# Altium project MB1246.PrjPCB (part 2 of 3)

## Sheet ST_LINK_V2-1.SCHDOC: ST-LINK/V2-1
size A4; DocumentNumber: MB1246; Revision: B.2; SheetNumber: 15; SheetTotal: 17; Project: STM32H7x3I-EVAL
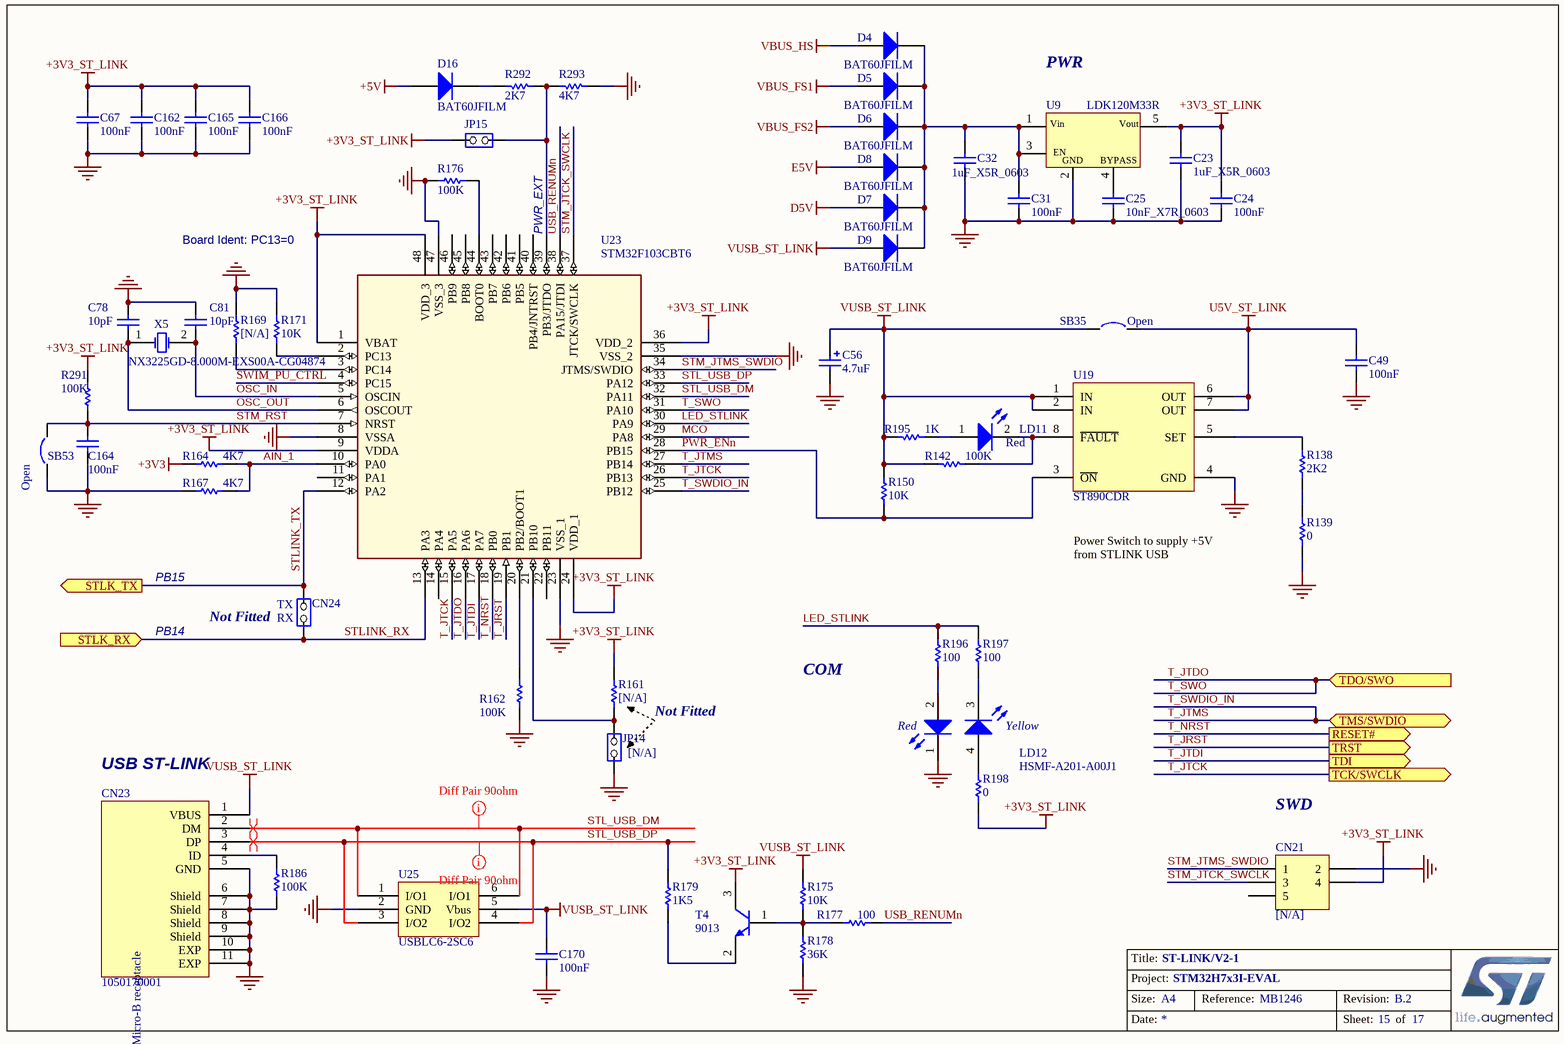
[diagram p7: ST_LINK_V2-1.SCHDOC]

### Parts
C23  1uF_X5R_0603  [0603C]
C24  100nF  [0603C]
C25  10nF_X7R_0603  [0603C]
C31  100nF  [0603C]
C32  1uF_X5R_0603  [0603C]
C49  100nF  [0603C]
C56  4.7uF  [TAN-A]
C67  100nF  [0603C]
C78  10pF  [0603C]
C81  10pF  [0603C]
C162  100nF  [0603C]
C164  100nF  [0603C]
C165  100nF  [0603C]
C166  100nF  [0603C]
C170  100nF  [0603C]
CN21  [N/A]  [HDR_2X3-1_2R54-6]
CN23  1050170001  [MICRO_USB_B_105017]
CN24  (no value)  [SIP2]
D4  BAT60JFILM  [SOD-323]
D5  BAT60JFILM  [SOD-323]
D6  BAT60JFILM  [SOD-323]
D7  BAT60JFILM  [SOD-323]
D8  BAT60JFILM  [SOD-323]
D9  BAT60JFILM  [SOD-323]
D16  BAT60JFILM  [SOD-323]
JP14  [N/A]  [SIP2]
JP15  (no value)  [SIP2]
LD11  Red  [0603D]
LD12  HSMF-A201-A00J1  [LED2_3528]
R138  2K2  [0402R]
R139  0  [0603R]
R142  100K  [0603R]
R150  10K  [0402R]
R161  [N/A]  [0603R]
R162  100K  [0603R]
R164  4K7  [0603R]
R167  4K7  [0603R]
R169  [N/A]  [0603R]
R171  10K  [0603R]
R175  10K  [0603R]
R176  100K  [0603R]
R177  100  [0603R]
R178  36K  [0603R]
R179  1K5  [0603R]
R186  100K  [0603R]
R195  1K  [0603R]
R196  100  [0603R]
R197  100  [0603R]
R198  0  [0603R]
R291  100K  [0603R]
R292  2K7  [0603R]
R293  4K7  [0603R]
SB35  Open  [SB_0603]
SB53  Open  [SB_0603]
T4  9013  [SOT-23]
U9  LDK120M33R  [SOT23-5]
U19  ST890CDR  [SOIC8_1R27_4R9X6]
U23  STM32F103CBT6  [LQFP48_0R5_9X9]
U25  USBLC6-2SC6  [SOT23-6L]
X5  NX3225GD-8.000M-EXS00A-CG04874  [XTAL_2SM_3R2X2R5_H1]

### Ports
RESET# (out), STLK_RX (in), STLK_TX (out), TCK/SWCLK (out), TDI (out), TDO/SWO (in), TMS/SWDIO (bidir), TRST (out)

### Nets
+3V3: R164.1
+3V3_ST_LINK: C23.1 C24.2 C67.2 C162.2 C165.2 C166.2 CN21.4 JP15.1(COMMON) R161.1 R198.2 R291.2 T4.3(C) U9.5(Vout) U23.1(VBAT) U23.9(VDDA) U23.24(VDD_1) U23.36(VDD_2) U23.48(VDD_3)
+5V: D16.1(A)
D5V: D7.1(A)
E5V: D8.1(A)
GND: C23.2 C24.1 C25.1 C31.1 C32.1 C49.1 C56.2 C67.1 C78.2 C81.2 C162.1 C164.1 C165.1 C166.1 C170.1 CN21.2 CN23.5(GND) CN23.6(Shield) CN23.7(Shield) CN23.8(Shield) CN23.9(Shield) CN23.10(EXP) CN23.11(EXP) JP14.1(COMMON) LD12.1(RED_cathode) R139.1 R162.1 R167.1 R169.1 R171.1 R176.1 R178.1 R186.2 R293.2 SB53.1 U9.2(GND) U19.4(GND) U23.8(VSSA) U23.23(VSS_1) U23.35(VSS_2) U23.47(VSS_3) U25.2(GND)
U5V_ST_LINK: C49.2 SB35.2 U19.6(OUT) U19.7(OUT)
VBUS_FS1: D5.1(A)
VBUS_FS2: D6.1(A)
VBUS_HS: D4.1(A)
VUSB_ST_LINK: C56.1 C170.2 CN23.1(VBUS) D9.1(A) R142.1 R150.1 R175.2 R195.1 SB35.1 U19.1(IN) U19.2(IN) U25.5(Vbus)
AIN_1: R164.2 R167.2 U23.10(PA0)
LED_STLINK: R196.1 R197.1 U23.30(PA9)
MCO: U23.29(PA8)
OSC_IN: C81.1 U23.5(OSCIN) X5.2(OSC2)
OSC_OUT: C78.1 U23.6(OSCOUT) X5.1(OSC1)
PWR_ENn: R150.2 U19.3(~{ON}) U23.28(PB15)
STL_USB_DM: CN23.2(DM) U23.32(PA11) U25.1(I/O1) U25.6(I/O1)
STL_USB_DP: CN23.3(DP) R179.1 U23.33(PA12) U25.3(I/O2) U25.4(I/O2)
STLINK_RX: CN24.1(COMMON) U23.13(PA3) ; port STLK_RX
STLINK_TX: CN24.2(NO) U23.12(PA2) ; port STLK_TX
STM_JTCK_SWCLK: CN21.3 U23.37(JTCK/SWCLK)
STM_JTMS_SWDIO: CN21.1 U23.34(JTMS/SWDIO)
STM_RST: C164.2 R291.1 SB53.2 U23.7(NRST)
SWIM_PU_CTRL: U23.4(PC15)
T_JRST: U23.19(PB1) ; port TRST  [project net PB4]
T_JTCK: U23.15(PA5) U23.26(PB13) ; port TCK/SWCLK  [project net PA14]
T_JTDI: U23.17(PA7) ; port TDI  [project net PA15]
T_JTDO: U23.16(PA6) U23.31(PA10) ; port TDO/SWO  [also labelled T_SWO]  [project net PB3]
T_JTMS: U23.25(PB12) U23.27(PB14) ; port TMS/SWDIO  [also labelled T_SWDIO_IN]  [project net PA13]
T_NRST: U23.18(PB0) ; port RESET#  [project net RESET#]
USB_RENUMn: R177.2 U23.38(PA15/JTDI)
NetC25_2: C25.2 U9.4(BYPASS)
NetC31_2: C31.2 C32.2 D4.2(K) D5.2(K) D6.2(K) D7.2(K) D8.2(K) D9.2(K) U9.1(Vin) U9.3(CE)
NetCN23_4: CN23.4(ID) R186.1
NetD16_2: D16.2(K) R292.1
NetJP14_2: JP14.2(NO) R161.2 U23.21(PB10)
NetJP15_2: JP15.2(NO) R292.2 R293.1 U23.39(PB3/JTDO)
NetLD11_1: LD11.1(A) R195.2
NetLD11_2: LD11.2(K) R142.2 U19.8(~{FAULT})
NetLD12_2: LD12.2(Red_anode) R196.2
NetLD12_3: LD12.3(YellowGreen_cathode) R197.2
NetLD12_4: LD12.4(YellowGreen_anode) R198.1
NetR138_1: R138.1 R139.2
NetR138_2: R138.2 U19.5(SET)
NetR162_2: R162.2 U23.20(PB2/BOOT1)
NetR169_2: R169.2 U23.3(PC14)
NetR171_2: R171.2 U23.2(PC13)
NetR175_1: R175.1 R177.1 R178.2 T4.1(B)
NetR176_2: R176.2 U23.44(BOOT0)
NetR179_2: R179.2 T4.2(E)

Not connected (* = marked no-connect by the designer): CN21 5; U23 11(PA1) 14(PA4) 22(PB11) 40(PB4/JNTRST) 41(PB5) 42(PB6) 43(PB7) 45(PB8) 46(PB9)

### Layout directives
differential pair: (no net found under the mark)
mark named Diff Pair 90ohm: STL_USB_DM, STL_USB_DP

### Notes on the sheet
- PWR
- Board Ident: PC13=0
- (near U23) PWR_EXT
- PB15
- Power Switch to supply +5V from STLINK USB
- PB14
- (near CN24) Not Fitted
- (near CN24) TX
- (near CN24) RX
- Not Fitted
- COM
- (near CN23) USB ST-LINK
- SWD

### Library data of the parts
C23 C32 = CAP SMD 0603  X5R 1µF 25V 10%: 0603  X5R 1µF; Rated voltage: 25V; Tolerance: 10%
C24 C31 C49 C67 C162 C164-C166 C170 = Capacitor_ST: Capacitor 0402 / 0603 / 0805
C25 = CAP SMD 0603  X7R 10000PF 50V 10%: 0603  X7R 10NF; Order code RS: 2040779; Rated voltage: 50V; Tolerance: 10%
C56 = Cap Pol1: Polarized Capacitor (Radial); Value: 100pF; Ordered by: Subcon
C78 C81 = Capacitor_ST: Capacitor 0402 / 0603 / 0805; Value: 100nF
CN21 = Header 3X2: Header, 3-Pin, Dual row
CN23 = 1050170001: Silkscreen: USB
CN24 = JP2: Fitted: NO
D4-D9 = BAT60JFILM: Manuf_1: STM; Provided: ST; ECCN_US/EU: EAR99/NEC
D16 = Diode: Default Diode; Code - JEDEC: DO-214-AB; Ordered by: STM; ECCN_US/EU: EAR99/NEC
JP14 = JP2
JP15 = JP2: Ordered by: Subcon; Silkscreen: Pwr_ext
LD11 = LED2: Typical RED, GREEN, YELLOW, AMBER GaAs LED
R138 R162 R176 R177 R179 R186 R291 = Resistor_ST: Resistor 0402 / 0603 / 0805; Description: Resistor 0402 or 0603 or 0805; Value: 10K
R139 R161 R175 R178 R196-R198 R292 R293 = Res1: Resistor; Value: 1K
R142 = Res1: Resistor; Value: 1K; Ordered by: Subcon
R150 R171 = Resistor_ST: Resistor 0402 / 0603 / 0805; Description: Resistor 0402 or 0603 or 0805
R164 R167 R169 = Resistor_ST: Resistor 0402 / 0603 / 0805; Description: Resistor 0402 or 0603 or 0805; Value: 10K; Fitted: NO
R195 = Res1: Resistor; Ordered by: Subcon
SB35 SB53 = Circuit Breaker
T4 = NPN: NPN Bipolar Transistor; Code - JEDEC: TO-226-AA
U9 = LDK120M33R: 200 mA low quiescent current very low noise LDO; Manuf_1: STM; Manuf_Part_1: LD3985M33R; Provided: ST; Description: Ultra low drop-low noise BiCMOS voltage, regulators low ESR capacitors compatible; Ref St: 9176161; ECCN_US/EU: EAR99/NEC
U23 = STM32F103CBT6: Medium-density performance line ARM-based 32-bit MCU with 64KB Flash; Manuf_Part_1: STM32F103C8T6; Manuf_1: STM; Ref St: 9175981; Provided: ST; ECCN_US/EU: 3A991A2/NEC
X5 = XTAL: Crystal Oscillator

## Sheet USB_OTG_FS.SchDoc: USB_OTG_FS
size A4; DocumentNumber: MB1246; Revision: B.2; SheetNumber: 9; SheetTotal: 17; Project: STM32H7x3I-EVAL
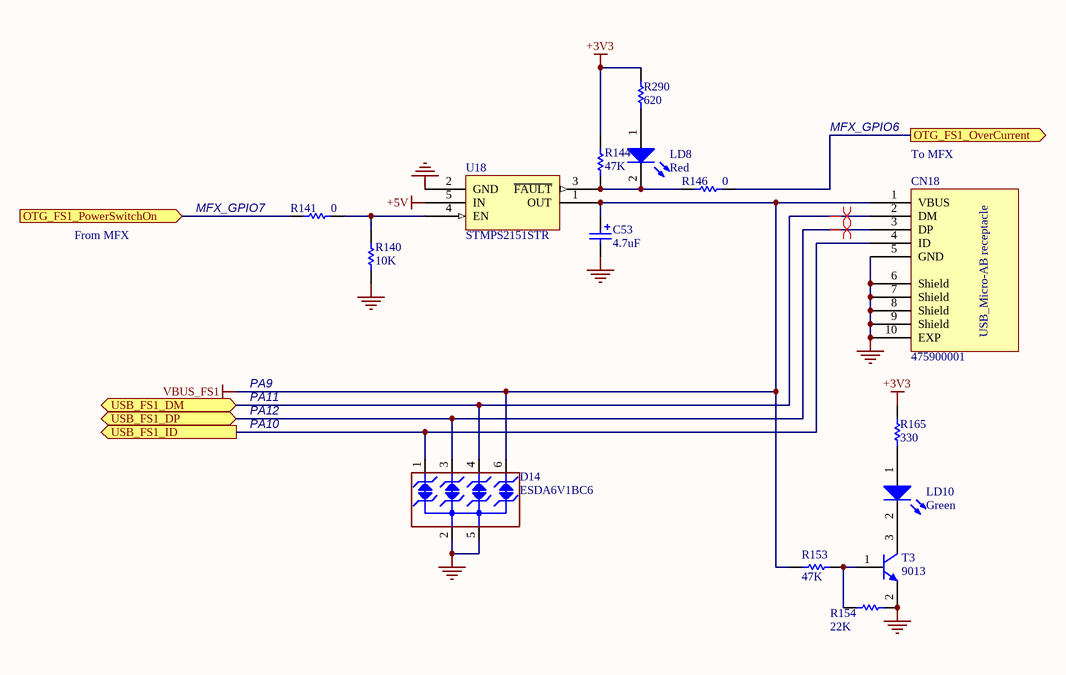
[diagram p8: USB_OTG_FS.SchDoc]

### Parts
C53  4.7uF  [TAN-A]
CN18  475900001  [MOLEX_47590001]
D14  ESDA6V1BC6  [SOT23-6L]
LD8  Red  [0603D]
LD10  Green  [0603D]
R140  10K  [0603R]
R141  0  [0603R]
R144  47K  [0603R]
R146  0  [0603R]
R153  47K  [0603R]
R154  22K  [0603R]
R165  330  [0603R]
R290  620  [0603R]
T3  9013  [SOT-23]
U18  STMPS2151STR  [SOT23-5]

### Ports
OTG_FS1_OverCurrent (out), OTG_FS1_PowerSwitchOn (in), USB_FS1_DM (bidir), USB_FS1_DP (bidir), USB_FS1_ID (out)

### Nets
+3V3: R144.1 R165.2 R290.2
+5V: U18.5(IN)
GND: C53.2 CN18.5(GND) CN18.6(Shield) CN18.7(Shield) CN18.8(Shield) CN18.9(Shield) CN18.10(EXP) D14.2(IO2) D14.5(IO4) R140.1 R154.1 T3.2(E) U18.2(GND)
VBUS_FS1: C53.1 CN18.1(VBUS) D14.6(NC) R153.1 U18.1(OUT)
PA10: CN18.4(ID) D14.1(IO1) ; port USB_FS1_ID
NetCN18_2: CN18.2(DM) D14.4(IO3) ; port USB_FS1_DM
NetCN18_3: CN18.3(DP) D14.3(GND) ; port USB_FS1_DP
NetLD8_1: LD8.1(A) R290.1
NetLD8_2: LD8.2(K) R144.2 R146.2 U18.3(~{FAULT})
NetLD10_1: LD10.1(A) R165.1
NetLD10_2: LD10.2(K) T3.3(C)
NetR140_2: R140.2 R141.1 U18.4(EN)
NetR141_2: R141.2 ; port OTG_FS1_PowerSwitchOn
NetR146_1: R146.1 ; port OTG_FS1_OverCurrent
NetR153_2: R153.2 R154.2 T3.1(B)

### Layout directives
differential pair: NetCN18_2, NetCN18_3

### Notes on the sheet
- MFX_GPIO6
- (near R141) MFX_GPIO7
- (near CN18) To MFX
- From MFX
- PA9
- PA11
- PA12
- PA10

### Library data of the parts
C53 = Cap Pol1: Polarized Capacitor (Radial); Value: 47uF
D14 = ESDA6V1BC6: 4-line ESD protection; Manuf_1: STM; Manuf_Part_1: ESDA5V3L; Description: Dual Transil array for ESD protection; Ref St: 9179034; Provided: ST; ECCN_US/EU: EAR99/NEC
LD8 LD10 = LED2: as LD11 on sheet ST_LINK_V2-1
R140 R141 R146 R290 = Res1: Resistor; Value: 1K
R144 R153 R154 R165 = res1: Resistor; Value: 1K
T3 = NPN: as T4 on sheet ST_LINK_V2-1
U18 = STMPS2141STR

## Sheet SD card.SchDoc: MICRO SD 3.0 Card
size A4; DocumentNumber: MB1246; Revision: B.2; SheetNumber: 12; SheetTotal: 17; Project: STM32H7x3I-EVAL
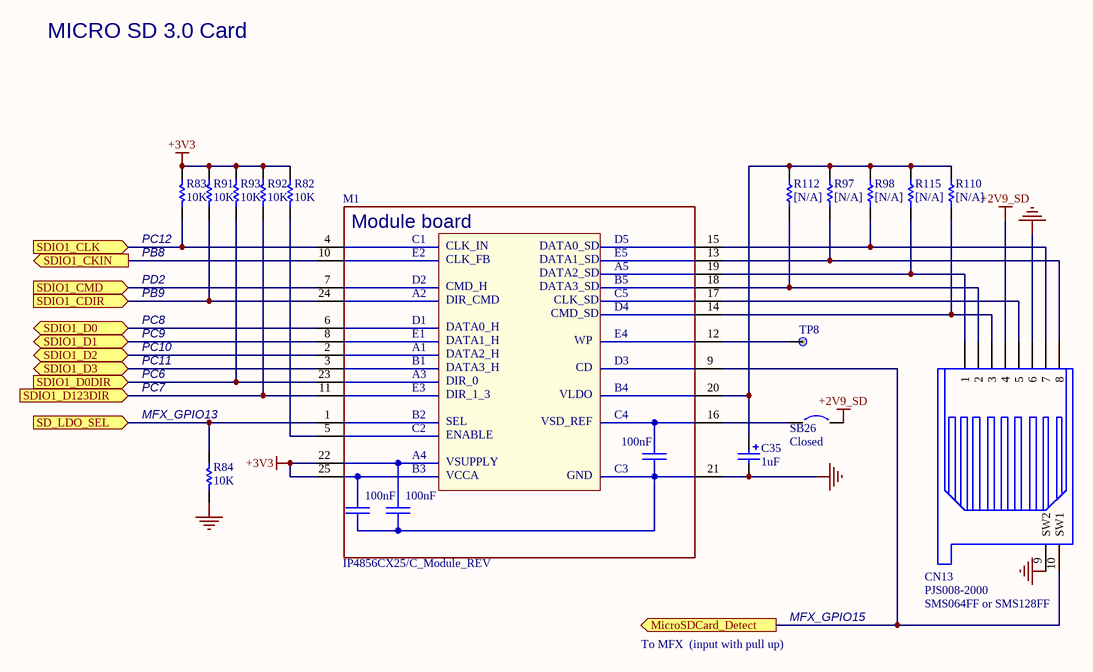
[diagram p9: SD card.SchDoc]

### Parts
C35  1uF  [TAN-A]
CN13  PJS008-2000  [MSD_PJS008_]
M1  IP4856CX25/C_Module_REV  [WLCSP25_0R4_MOUDLE_REV]
R82  10K  [0603R]
R83  10K  [0603R]
R84  10K  [0603R]
R91  10K  [0603R]
R92  10K  [0603R]
R93  10K  [0603R]
R97  [N/A]  [0603R]
R98  [N/A]  [0603R]
R110  [N/A]  [0603R]
R112  [N/A]  [0603R]
R115  [N/A]  [0603R]
SB26  Closed  [SB_0603]
TP8  (no value)  [TP]

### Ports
MicroSDCard_Detect (out), SD_LDO_SEL (in), SDIO1_CDIR (in), SDIO1_CKIN (out), SDIO1_CLK (in), SDIO1_CMD (in), SDIO1_D0 (bidir), SDIO1_D0DIR (in), SDIO1_D1 (bidir), SDIO1_D2 (bidir), SDIO1_D3 (bidir), SDIO1_D123DIR (in)

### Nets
+2V9_SD: CN13.4 SB26.1
+3V3: M1.22(CD) M1.25(GND) R82.2 R83.2 R91.2 R92.2 R93.2
GND: C35.2 CN13.6 CN13.9(SW2) M1.21(WP) R84.1
PB8: M1.10(DIR_1_3) ; port SDIO1_CKIN
PB9: M1.24(VSD_REF) R91.1 ; port SDIO1_CDIR
PC7: M1.11(SEL) R92.1 ; port SDIO1_D123DIR
PC8: M1.6(DATA1_H) ; port SDIO1_D0
PC9: M1.8(DATA3_H) ; port SDIO1_D1
PC10: M1.2(CLK_FB) ; port SDIO1_D2
PC11: M1.3(CMD_H) ; port SDIO1_D3
PC12: M1.4(DIR_CMD) R83.1 ; port SDIO1_CLK
PD2: M1.7(DATA2_H) ; port SDIO1_CMD
NetC35_1: C35.1 M1.20(CMD_SD) R97.1 R98.1 R110.1 R112.1 R115.1
NetCN13_1: CN13.1 M1.19(CLK_SD) R115.2
NetCN13_2: CN13.2 M1.18(DATA3_SD) R112.2
NetCN13_3: CN13.3 M1.14(VCCA) R110.2
NetCN13_5: CN13.5 M1.17(DATA2_SD)
NetCN13_7: CN13.7 M1.15(DATA0_SD) R98.2
NetCN13_8: CN13.8 M1.13(VSUPPLY) R97.2
NetCN13_10: CN13.10(SW1) M1.9(DIR_0) ; port MicroSDCard_Detect
NetM1_1: M1.1(CLK_IN) R84.2 ; port SD_LDO_SEL
NetM1_5: M1.5(DATA0_H) R82.1
NetM1_12: M1.12(ENABLE) TP8.1
NetM1_16: M1.16(DATA1_SD) SB26.2
NetM1_23: M1.23(VLDO) R93.1 ; port SDIO1_D0DIR

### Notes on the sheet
- MICRO SD 3.0 Card
- PC12
- PB8
- PB9
- PD2
- PC6
- PC8
- PC9
- PC10
- PC11
- PC7
- (near R84) MFX_GPIO13
- To MFX  (input with pull up)
- MFX_GPIO15
- SMS064FF or SMS128FF

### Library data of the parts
C35 = Cap Pol1: Polarized Capacitor (Radial); Value: 10uF
CN13 = SMS016AFA5E
M1 = IP4856CX25/C_Module_REV: SDcard3.0 dual voltage level  translator; ECCN_US/EU: 3A991
R82-R84 R91-R93 = Res1: Resistor; Value: 1K
R97 R98 R110 R112 R115 = res1: Resistor; Value: 1K
SB26 = Circuit Breaker_close: Circuit Breaker
TP8 = TP

## Sheet JTAG&Trace.SchDoc: JTAG & Trace
size A4; DocumentNumber: MB1246; Revision: B.2; SheetNumber: 17; SheetTotal: 17; Project: STM32H7x3I-EVAL
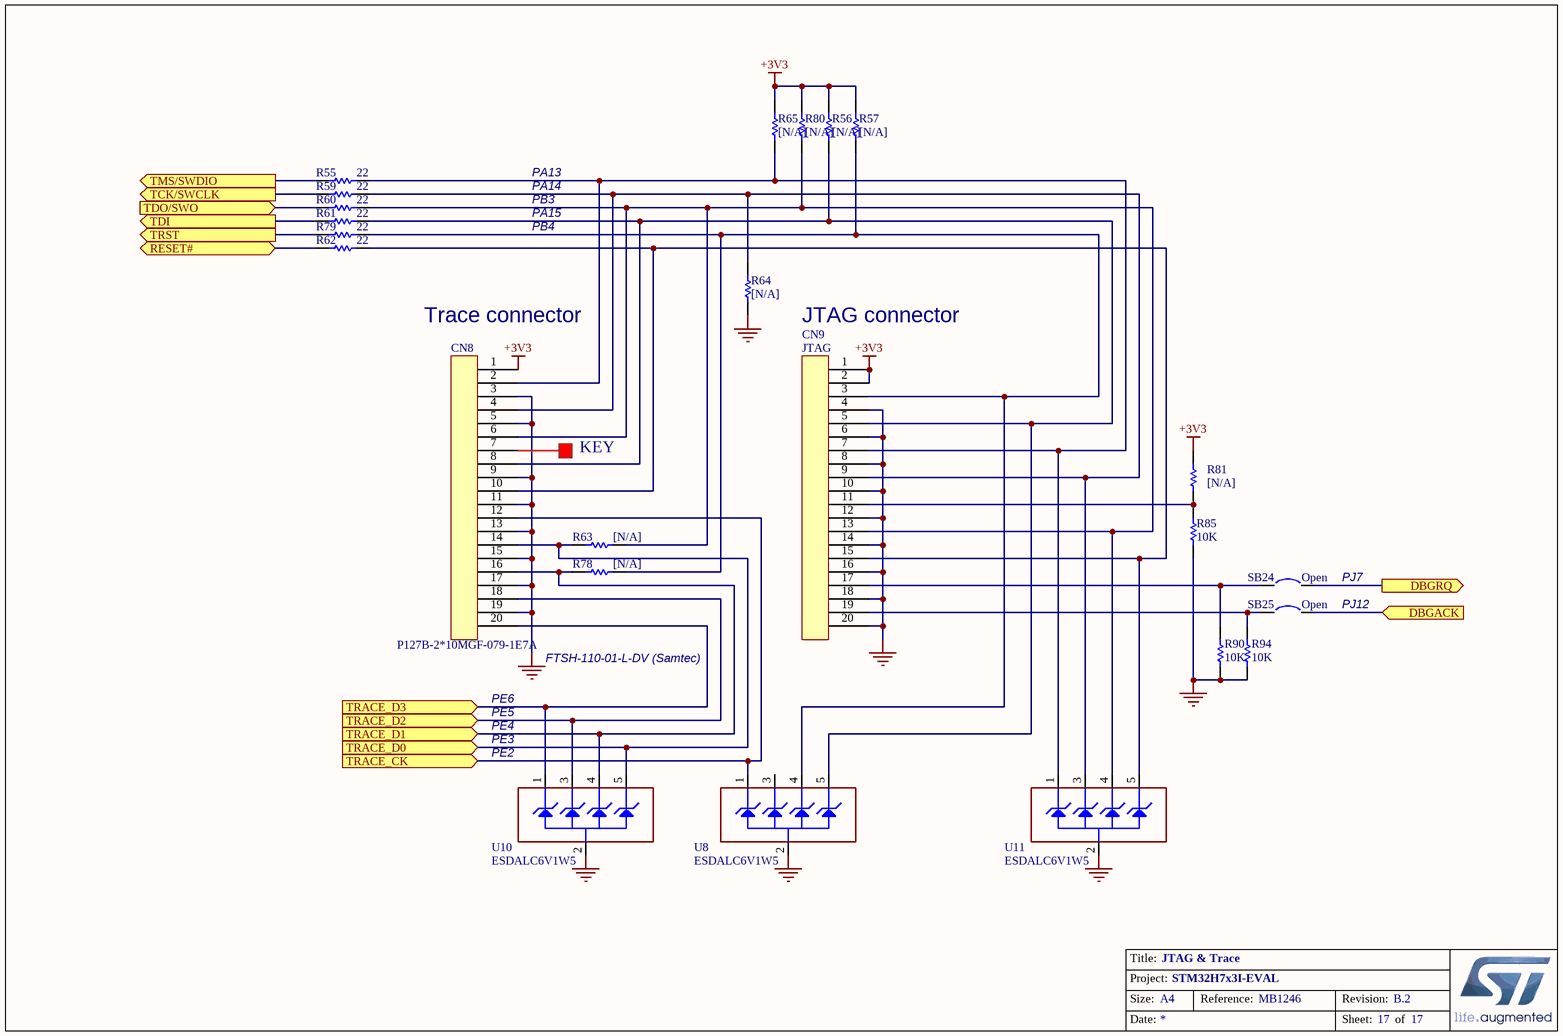
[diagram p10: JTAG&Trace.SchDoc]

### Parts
CN8  P127B-2*10MGF-079-1E7A  [FTSH-110-01-L-DV]
CN9  JTAG  [IDC20S]
R55  22  [0603R]
R56  [N/A]  [0603R]
R57  [N/A]  [0603R]
R59  22  [0603R]
R60  22  [0603R]
R61  22  [0603R]
R62  22  [0603R]
R63  [N/A]  [0603R]
R64  [N/A]  [0603R]
R65  [N/A]  [0603R]
R78  [N/A]  [0603R]
R79  22  [0603R]
R80  [N/A]  [0603R]
R81  [N/A]  [0603R]
R85  10K  [0603R]
R90  10K  [0603R]
R94  10K  [0603R]
SB24  Open  [SB_0603]
SB25  Open  [SB_0603]
U8  ESDALC6V1W5  [SOT-353]
U10  ESDALC6V1W5  [SOT-353]
U11  ESDALC6V1W5  [SOT-353]

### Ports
DBGACK (in), DBGRQ (out), RESET# (bidir), TCK/SWCLK (out), TDI (out), TDO/SWO (in), TMS/SWDIO (out), TRACE_CK (in), TRACE_D0 (in), TRACE_D1 (in), TRACE_D2 (in), TRACE_D3 (in), TRST (out)

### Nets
+3V3: CN8.1 CN9.1 CN9.2 R56.2 R57.2 R65.2 R80.2 R81.2
GND: CN8.3 CN8.5 CN8.9 CN8.11 CN8.13 CN8.15 CN8.17 CN8.19 CN9.4 CN9.6 CN9.8 CN9.10 CN9.12 CN9.14 CN9.16 CN9.18 CN9.20 R64.1 R85.1 R90.1 R94.1 U8.2(GND) U10.2(GND) U11.2(GND)
LCD_B0: SB25.2 ; port DBGACK
LCD_G0: SB24.2 ; port DBGRQ
PA13: R55.2 ; port TMS/SWDIO
PA14: R59.2 ; port TCK/SWCLK
PA15: R61.2 ; port TDI
PB3: R60.2 ; port TDO/SWO
PB4: R79.2 ; port TRST
RESET#: R62.2 ; port RESET#
NetCN8_2: CN8.2 CN9.7 R55.1 R65.1 U11.1(IO1)
NetCN8_4: CN8.4 CN9.9 R59.1 R64.2 U11.3(IO2)
NetCN8_6: CN8.6 CN9.13 R60.1 R63.2 R80.1 U11.4(IO3)
NetCN8_8: CN8.8 CN9.5 R56.1 R61.1 U8.5(IO4)
NetCN8_10: CN8.10 CN9.15 R62.1 U11.5(IO4)
NetCN8_12: CN8.12 U8.1(IO1) ; port TRACE_CK
NetCN8_14: CN8.14 R63.1 U10.5(IO4) ; port TRACE_D0
NetCN8_16: CN8.16 R78.1 U10.4(IO3) ; port TRACE_D1
NetCN8_18: CN8.18 U10.3(IO2) ; port TRACE_D2
NetCN8_20: CN8.20 U10.1(IO1) ; port TRACE_D3
NetCN9_3: CN9.3 R57.1 R78.2 R79.1 U8.4(IO3)
NetCN9_11: CN9.11 R81.1 R85.2
NetCN9_17: CN9.17 R90.2 SB24.1
NetCN9_19: CN9.19 R94.2 SB25.1

Not connected (* = marked no-connect by the designer): CN8 7; U8 3(IO2)

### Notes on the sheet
- PA13
- PA14
- PB3
- PA15
- PB4
- (near CN8) Trace connector
- JTAG connector
- KEY
- PJ7
- PJ12
- PE6
- PE5
- (near CN8) FTSH-110-01-L-DV (Samtec)
- PE4
- PE3
- (near U10) PE2

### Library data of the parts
CN8 CN9 = 20PIN1
R55-R57 R59-R65 R78-R81 R85 R90 R94 = Res1: Resistor; Value: 1K
SB24 SB25 = Circuit Breaker
U8 U10 U11 = ESDALC6V1W5: Dual Transil array for ESD protection; Manuf_1: STM; Manuf_Part_1: ESDA5V3L; Ref St: 9179034; Provided: ST; ECCN_US/EU: EAR99/NEC

## Sheet Ethernet.SchDoc: Ethernet
size A4; DocumentNumber: MB1246; Revision: B.2; SheetNumber: 7; SheetTotal: 17; Project: STM32H7x3I-EVAL
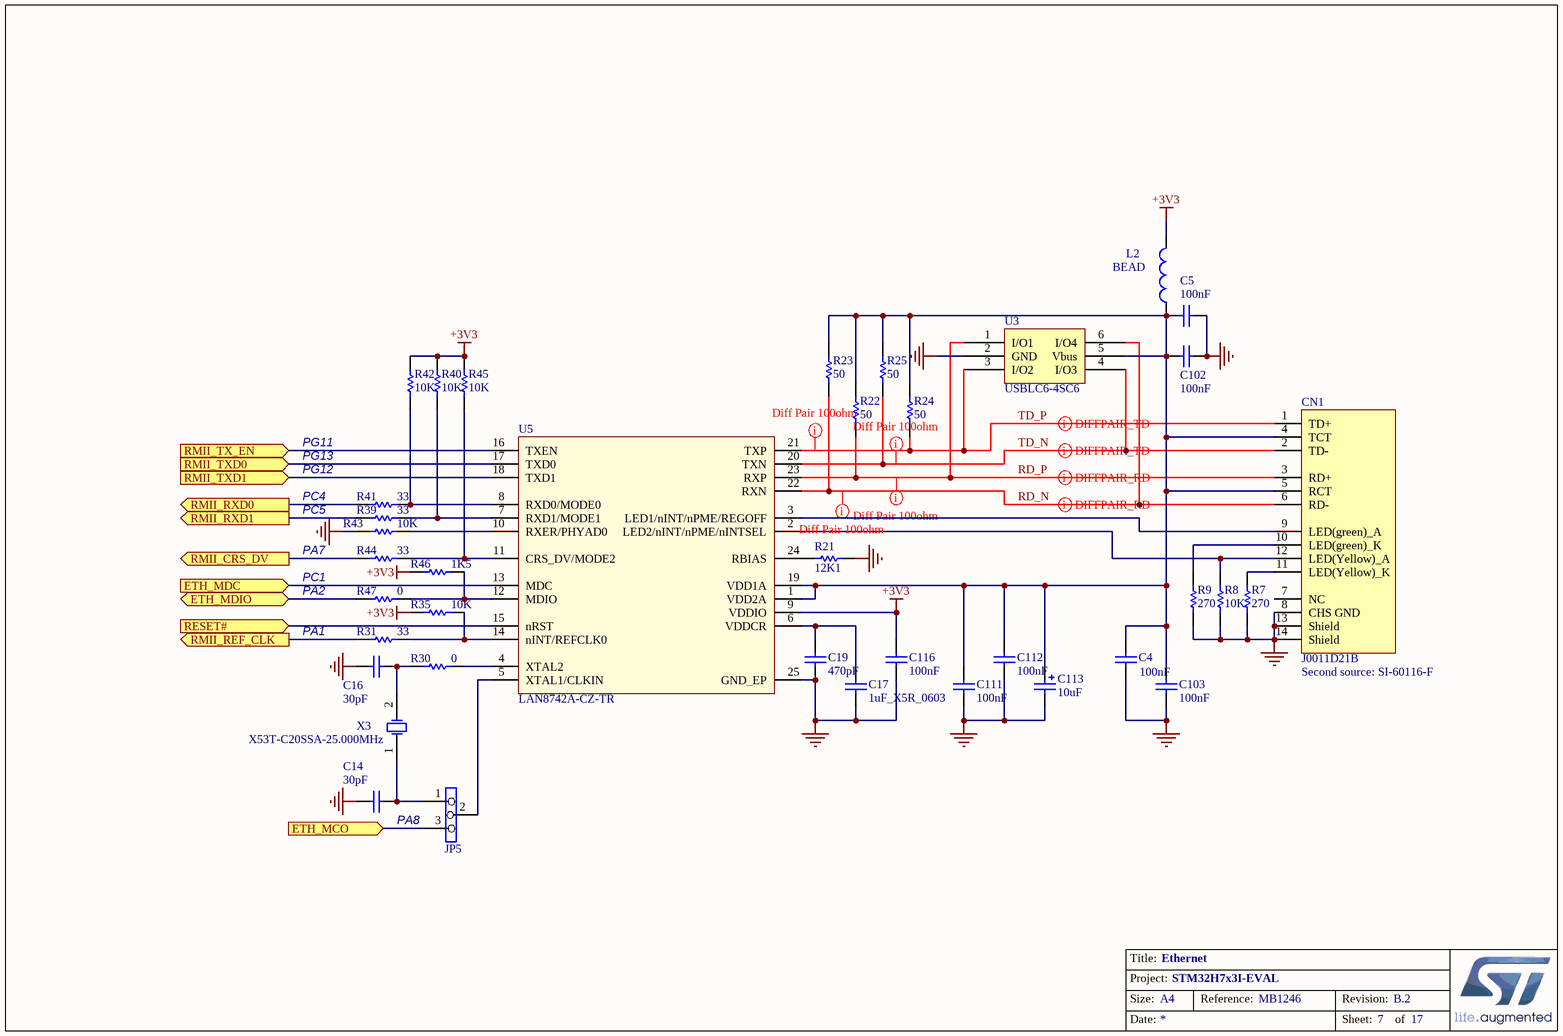
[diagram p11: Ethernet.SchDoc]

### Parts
C4  100nF  [0603C]
C5  100nF  [0603C]
C14  30pF  [0603C]
C16  30pF  [0603C]
C17  1uF_X5R_0603  [0603C]
C19  470pF  [0603C]
C102  100nF  [0603C]
C103  100nF  [0603C]
C111  100nF  [0603C]
C112  100nF  [0603C]
C113  10uF  [TAN-A]
C116  100nF  [0603C]
CN1  J0011D21B  [RJ45_J0011D01BNL]
JP5  (no value)  [SIP3]
L2  BEAD  [0603L]
R7  270  [0603R]
R8  10K  [0603R]
R9  270  [0603R]
R21  12K1  [0603R]
R22  50  [0603R]
R23  50  [0603R]
R24  50  [0603R]
R25  50  [0603R]
R30  0  [0603R]
R31  33  [0603R]
R35  10K  [0603R]
R39  33  [0603R]
R40  10K  [0603R]
R41  33  [0603R]
R42  10K  [0603R]
R43  10K  [0603R]
R44  33  [0603R]
R45  10K  [0603R]
R46  1K5  [0603R]
R47  0  [0603R]
U3  USBLC6-4SC6  [SOT23-6]
U5  LAN8742A-CZ-TR  [QFN24_0R5_4X4]
X3  X53T-C20SSA-25.000MHz  [XTAL_2SM_5X3R2]

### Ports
ETH_MCO (in), ETH_MDC (in), ETH_MDIO (bidir), RESET# (in), RMII_CRS_DV (out), RMII_REF_CLK (out), RMII_RXD0 (out), RMII_RXD1 (out), RMII_TX_EN (in), RMII_TXD0 (in), RMII_TXD1 (in)

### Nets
+3V3: C116.2 L2.2 R35.1 R40.1 R42.1 R45.1 R46.2 U5.9(VDDIO)
GND: C4.1 C5.1 C14.2 C16.2 C17.2 C19.1 C102.1 C103.1 C111.1 C112.1 C113.2 C116.1 CN1.8(CHS_GND) CN1.13(Shield) CN1.14(Shield) R7.2 R8.2 R9.2 R21.2 R43.2 U3.2(GND) U5.25(GND_EP)
PA1: R31.2 ; port RMII_REF_CLK
PA2: R47.2 ; port ETH_MDIO
PA7: R44.2 ; port RMII_CRS_DV
PA8: JP5.3 ; port ETH_MCO
PC4: R41.2 ; port RMII_RXD0
PC5: R39.2 ; port RMII_RXD1
PG11: U5.16(TXEN) ; port RMII_TX_EN
PG12: U5.18(TXD1) ; port RMII_TXD1
PG13: U5.17(TXD0) ; port RMII_TXD0
RD_N: CN1.6(RD-) R23.1 U3.6(I/O4) U5.22(RXN)
RD_P: CN1.3(RD+) R22.1 U3.1(I/O1) U5.23(RXP)
RESET#: U5.15(nRST) ; port RESET#
TD_N: CN1.2(TD-) R25.1 U3.4(I/O3) U5.20(TXN)
TD_P: CN1.1(TD+) R24.1 U3.3(I/O2) U5.21(TXP)
NetC4_2: C4.2 C5.2 C102.2 C103.2 C111.2 C112.2 C113.1 CN1.4(TCT) CN1.5(RCT) L2.1 R22.2 R23.2 R24.2 R25.2 U3.5(Vbus) U5.1(VDD2A) U5.19(VDD1A)
NetC14_1: C14.1 JP5.1 X3.1(OSC1)
NetC16_1: C16.1 R30.2 X3.2(OSC2)
NetC17_1: C17.1 C19.2 U5.6(VDDCR)
NetCN1_9: CN1.9(LED(green)_A) U5.3(LED1/nINT/nPME/REGOFF)
NetCN1_10: CN1.10(LED(green)_K) R9.1
NetCN1_11: CN1.11(LED(Yellow)_K) R7.1
NetCN1_12: CN1.12(LED(Yellow)_A) R8.1 U5.2(LED2/nINT/nPME/nINTSEL)
NetJP5_2: JP5.2 U5.5(XTAL1/CLKIN)
NetR21_1: R21.1 U5.24(RBIAS)
NetR30_1: R30.1 U5.4(XTAL2)
NetR31_1: R31.1 R35.2 U5.14(nINT/REFCLK0)
NetR39_1: R39.1 R40.2 U5.7(RXD1/MODE1)
NetR41_1: R41.1 R42.2 U5.8(RXD0/MODE0)
NetR43_1: R43.1 U5.10(RXER/PHYAD0)
NetR44_1: R44.1 R45.2 U5.11(CRS_DV/MODE2)
NetR46_1: R46.1 R47.1 U5.12(MDIO)
NetSB38_1: U5.13(MDC) ; port ETH_MDC

Not connected (* = marked no-connect by the designer): CN1 7(NC)

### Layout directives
differential pair: RD_N, RD_P, TD_N, TD_P
rule Matched Net Lengths [Tolerance = 100mil]: RD_N, RD_P, TD_N, TD_P

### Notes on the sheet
- PG11
- PG13
- PG12
- PC4
- PC5
- PA7
- PC1
- PA2
- PA1
- (near CN1) Second source: SI-60116-F
- PA8

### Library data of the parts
C4 C5 C102 C103 C111 C112 C116 = Capacitor_ST: Capacitor 0402 / 0603 / 0805
C14 C16 C19 = Capacitor_ST: as C78 on sheet ST_LINK_V2-1
C17 = CAP SMD 0603  X5R 1µF 25V 10%: as C23 on sheet ST_LINK_V2-1
C113 = Cap_10uF_POL_10%_TANA: Polarized Capacitor,10uF,10V,10%,typeA,VISHAY; Manuf_Part_1: 293D106X9010A2TE3
JP5 = Jumper3
L2 = Inductor: Value: 100uH
R7 R9 = Resistor_ST: as R138 on sheet ST_LINK_V2-1
R8 R35 R40 R42 R43 R45 = Resistor_ST: as R150 on sheet ST_LINK_V2-1
R21 = Res_12K1_1%_0603: Resistor,12K1,0603,1%,VISHAY; Manuf_Part_1: MCT 0603-50 1% P5 12K1; Order: 2325243
R22-R25 = Res_50_1%_0603: Resistor,50,0603,1%,YAGEO; Manuf_Part_1: RC0402FR-0750RL; Description: Resistor,50,0402,1%,YAGEO
R30 R47 = Res1: Resistor; Value: 1K
R31 R39 R41 R44 = Res_33_1%_0402: Resistor,33,0402,1%,YAGEO; Manuf_Part_1: RC0402FR-0733RL
R46 = Res_1K5_1%_0402: Resistor,1K5,0402,1%,YAGEO; Manuf_Part_1: RC0402FR-071K5L
U5 = LAN8742A-CZ-TR: LAN8742A-CZ-TR - Small Footprint RMII 10/100 Ethernet, Transceiver with HP Auto-MDIX and flexPWR Technology SQFN-24; Manuf_1: MICROCHIP
X3 = XTAL_5032: Crystal Oscillator

## Sheet RS232.SchDoc: RS232
size A4; DocumentNumber: MB1246; Revision: B.2; SheetNumber: 10; SheetTotal: 17; Project: STM32H7x3I-EVAL
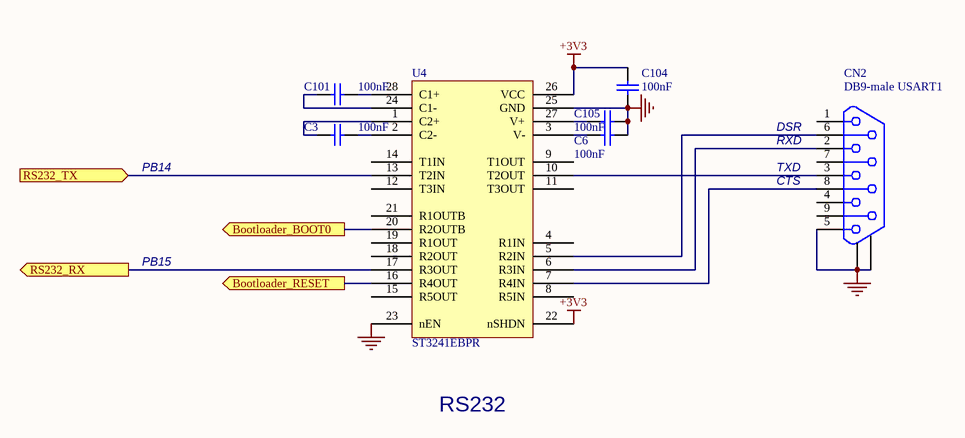
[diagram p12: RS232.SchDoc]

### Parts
C3  100nF  [0603C]
C6  100nF  [0603C]
C101  100nF  [0603C]
C104  100nF  [0603C]
C105  100nF  [0603C]
CN2  DB9-male USART1  [DB9/M]
U4  ST3241EBPR  [SSOP28_0R65_10R2X7R8]

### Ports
Bootloader_BOOT0 (out), Bootloader_RESET (out), RS232_RX (out), RS232_TX (in)

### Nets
+3V3: C104.1 U4.22(nSHDN) U4.26(VCC)
GND: C6.1 C104.2 C105.1 CN2.5 CN2.10 CN2.11 U4.23(nEN) U4.25(GND)
NetC3_1: C3.1 U4.1(C2+)
NetC3_2: C3.2 U4.2(C2-)
NetC6_2: C6.2 U4.3(V-)
NetC101_1: C101.1 U4.24(C1-)
NetC101_2: C101.2 U4.28(C1+)
NetC105_2: C105.2 U4.27(V+)
NetCN2_2: CN2.2 U4.6(R3IN)
NetCN2_3: CN2.3 U4.10(T2OUT)
NetCN2_6: CN2.6 U4.5(R2IN)
NetCN2_8: CN2.8 U4.7(R4IN)
NetD3_1: U4.20(R2OUTB) ; port Bootloader_BOOT0
NetJP6_2: U4.16(R4OUT) ; port Bootloader_RESET
NetJP7_1: U4.13(T2IN) ; port RS232_TX
NetJP8_1: U4.17(R3OUT) ; port RS232_RX

Not connected (* = marked no-connect by the designer): CN2 1 4 7 9; U4 4(R1IN) 8(R5IN) 9(T1OUT) 11(T3OUT) 12(T3IN) 14(T1IN) 15(R5OUT) 18(R2OUT) 19(R1OUT) 21(R1OUTB)

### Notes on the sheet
- PB14
- (near CN2) RXD
- (near CN2) TXD
- (near CN2) DSR
- (near CN2) CTS
- PB15
- RS232

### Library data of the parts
C3 C6 C101 C104 C105 = Cap: Capacitor; Value: 10nF
CN2 = DB9-USART
U4 = ST3241

## Sheet Peripherals.SchDoc: Peripherals
size A4; DocumentNumber: MB1246; Revision: B.2; SheetNumber: 13; SheetTotal: 17; Project: STM32H7x3I-EVAL
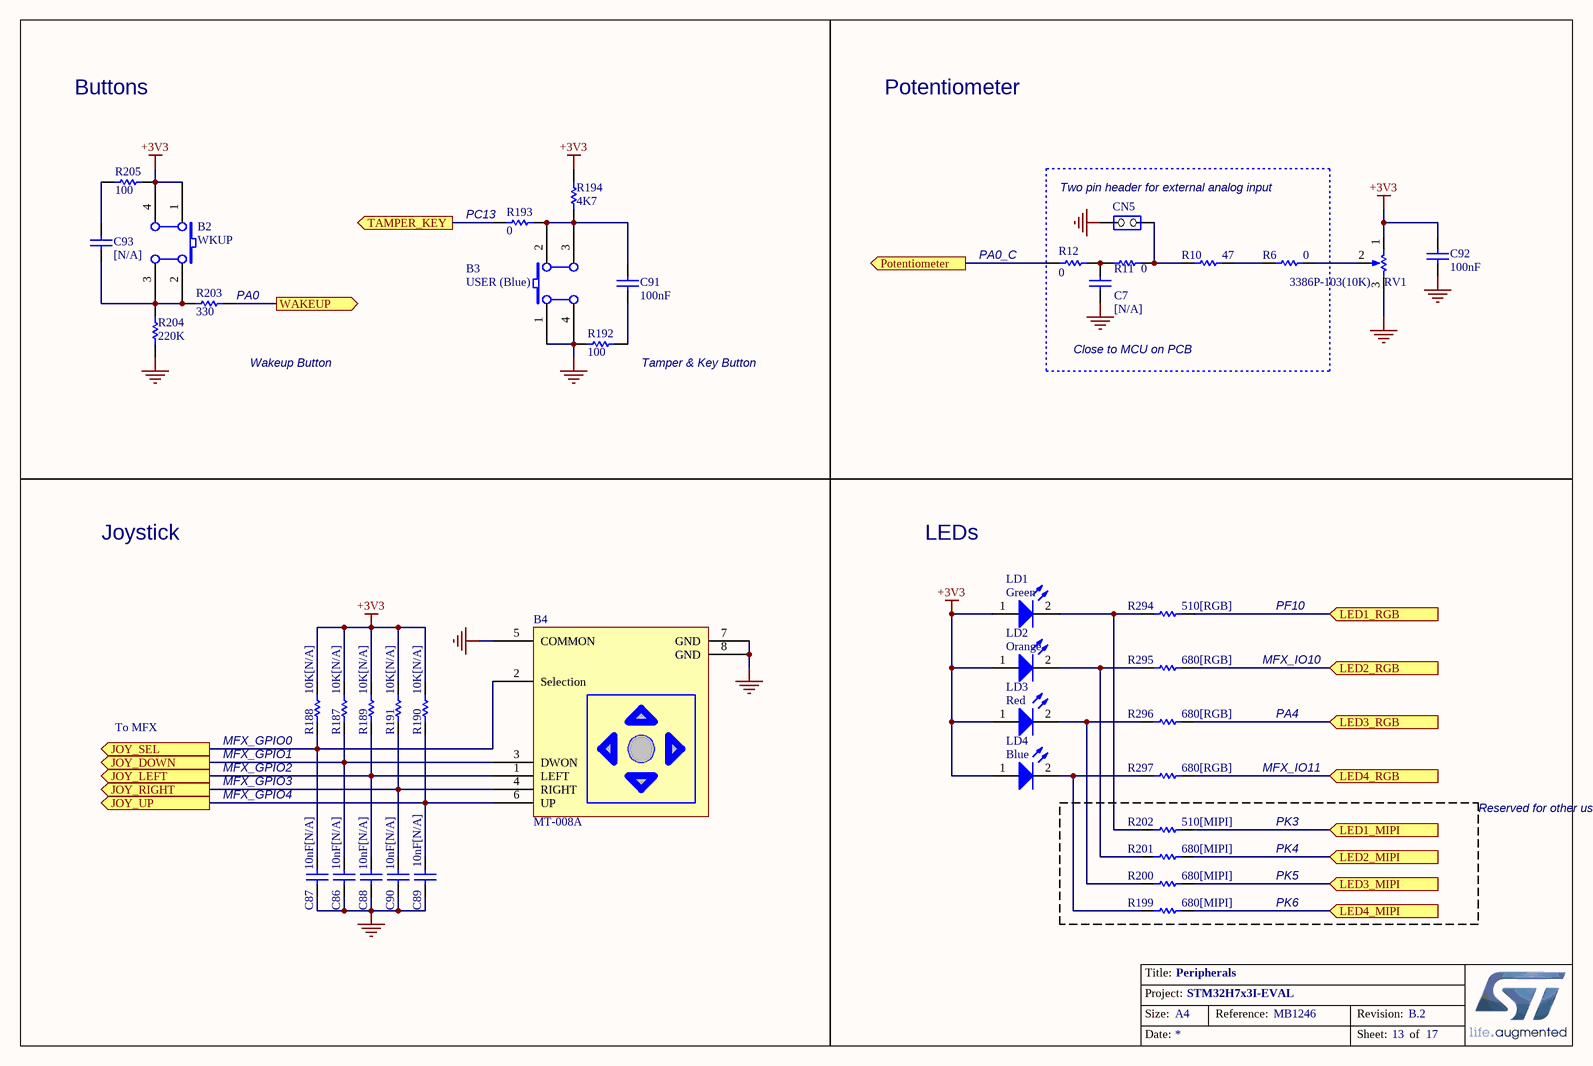
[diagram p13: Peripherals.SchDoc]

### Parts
B2  WKUP  [PB10]
B3  USER (Blue)  [PB10]
B4  MT-008A  [MT-008A]
C7  [N/A]  [0603C]
C86  10nF[N/A]  [0603C]
C87  10nF[N/A]  [0603C]
C88  10nF[N/A]  [0603C]
C89  10nF[N/A]  [0603C]
C90  10nF[N/A]  [0603C]
C91  100nF  [0603C]
C92  100nF  [0603C]
C93  [N/A]  [0603C]
CN5  (no value)  [SIP2]
LD1  Green  [0603D]
LD2  Orange  [0603D]
LD3  Red  [0603D]
LD4  Blue  [0603D]
R6  0  [0603R]
R10  47  [0603R]
R11  0  [0603R]
R12  0  [0603R]
R187  10K[N/A]  [0603R]
R188  10K[N/A]  [0603R]
R189  10K[N/A]  [0603R]
R190  10K[N/A]  [0603R]
R191  10K[N/A]  [0603R]
R192  100  [0603R]
R193  0  [0603R]
R194  4K7  [0603R]
R199  680[MIPI]  [0603R]
R200  680[MIPI]  [0603R]
R201  680[MIPI]  [0603R]
R202  510[MIPI]  [0603R]
R203  330  [0603R]
R204  220K  [0603R]
R205  100  [0603R]
R294  510[RGB]  [0603R]
R295  680[RGB]  [0603R]
R296  680[RGB]  [0603R]
R297  680[RGB]  [0603R]
RV1  3386P-103(10K)  [3386P]

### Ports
JOY_DOWN (out), JOY_LEFT (out), JOY_RIGHT (out), JOY_SEL (out), JOY_UP (out), LED1_MIPI (in), LED1_RGB (in), LED2_MIPI (in), LED2_RGB (in), LED3_MIPI (in), LED3_RGB (in), LED4_MIPI (in), LED4_RGB (in), Potentiometer (out), TAMPER_KEY (out), WAKEUP (out)

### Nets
+3V3: B2.1(A0) B2.4(A1) C92.1 LD1.1(A) LD2.1(A) LD3.1(A) LD4.1(A) R187.1 R188.1 R189.1 R190.1 R191.1 R194.2 R205.1 RV1.1(BOT)
GND: B3.1(A0) B3.4(A1) B4.5(COMMON) B4.7(GND) B4.8(GND) C7.1 C86.1 C87.1 C88.1 C89.1 C90.1 C92.2 CN5.2(NO) R192.1 R204.2 RV1.3(TOP)
LCD_B4: R202.1 ; port LED1_MIPI
LCD_B5: R201.1 ; port LED2_MIPI
LCD_B6: R200.1 ; port LED3_MIPI
LCD_B7: R199.1 ; port LED4_MIPI
PA0: R203.2 ; port WAKEUP
PA4: R296.1 ; port LED3_RGB
PC13: R193.2 ; port TAMPER_KEY
PF10: R294.1 ; port LED1_RGB
NetB2_2: B2.2(B0) B2.3(B1) C93.2 R203.1 R204.1
NetB3_2: B3.2(B0) B3.3(B1) C91.2 R193.1 R194.1
NetB4_1: B4.1(LEFT) C88.2 R189.2 ; port JOY_LEFT
NetB4_2: B4.2(Selection) C87.2 R188.2 ; port JOY_SEL
NetB4_3: B4.3(DWON) C86.2 R187.2 ; port JOY_DOWN
NetB4_4: B4.4(RIGHT) C90.2 R191.2 ; port JOY_RIGHT
NetB4_6: B4.6(UP) C89.2 R190.2 ; port JOY_UP
NetC7_2: C7.2 R11.1 R12.1
NetC91_1: C91.1 R192.2
NetC93_1: C93.1 R205.2
NetCN5_1: CN5.1(COMMON) R10.1 R11.2
NetLD1_2: LD1.2(K) R202.2 R294.2
NetLD2_2: LD2.2(K) R201.2 R295.2
NetLD3_2: LD3.2(K) R200.2 R296.2
NetLD4_2: LD4.2(K) R199.2 R297.2
NetR6_1: R6.1 R10.2
NetR6_2: R6.2 RV1.2(TAP)
NetR12_2: R12.2 ; port Potentiometer
NetR295_1: R295.1 ; port LED2_RGB
NetR297_1: R297.1 ; port LED4_RGB

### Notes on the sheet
- Buttons
- Potentiometer
- (near CN5) Two pin header for external analog input
- (near R193) PC13
- (near R12) PA0_C
- (near R203) PA0
- Wakeup Button
- (near R192) Tamper & Key Button
- Close to MCU on PCB
- Joystick
- LEDs
- MFX_IO10
- PF10
- To MFX
- PA4
- (near R188) MFX_GPIO0
- MFX_GPIO1
- MFX_GPIO2
- MFX_GPIO3
- MFX_GPIO4
- MFX_IO11
- PK3
- PK4
- Reserved for other use
- PK5
- PK6

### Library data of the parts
B2 B3 = SW PUSHBUTTON: SE PUSHBUTTON
C7 = cap: Capacitor; Value: 100pF
C86-C93 = CAP: Capacitor; Value: 100pF
CN5 = JP2
LD1-LD4 = LED2: as LD11 on sheet ST_LINK_V2-1
R6 R10-R12 R192 R193 R199-R203 R205 R294-R297 = Res1: Resistor; Value: 1K
R187-R191 R194 R204 = res1: Resistor; Value: 1K
RV1 = RV

## Sheet MCU.SchDoc: MCU
size A3; DocumentNumber: MB1246; Revision: B.2; SheetNumber: 2; SheetTotal: 17; Project: STM32H7x3I-EVAL
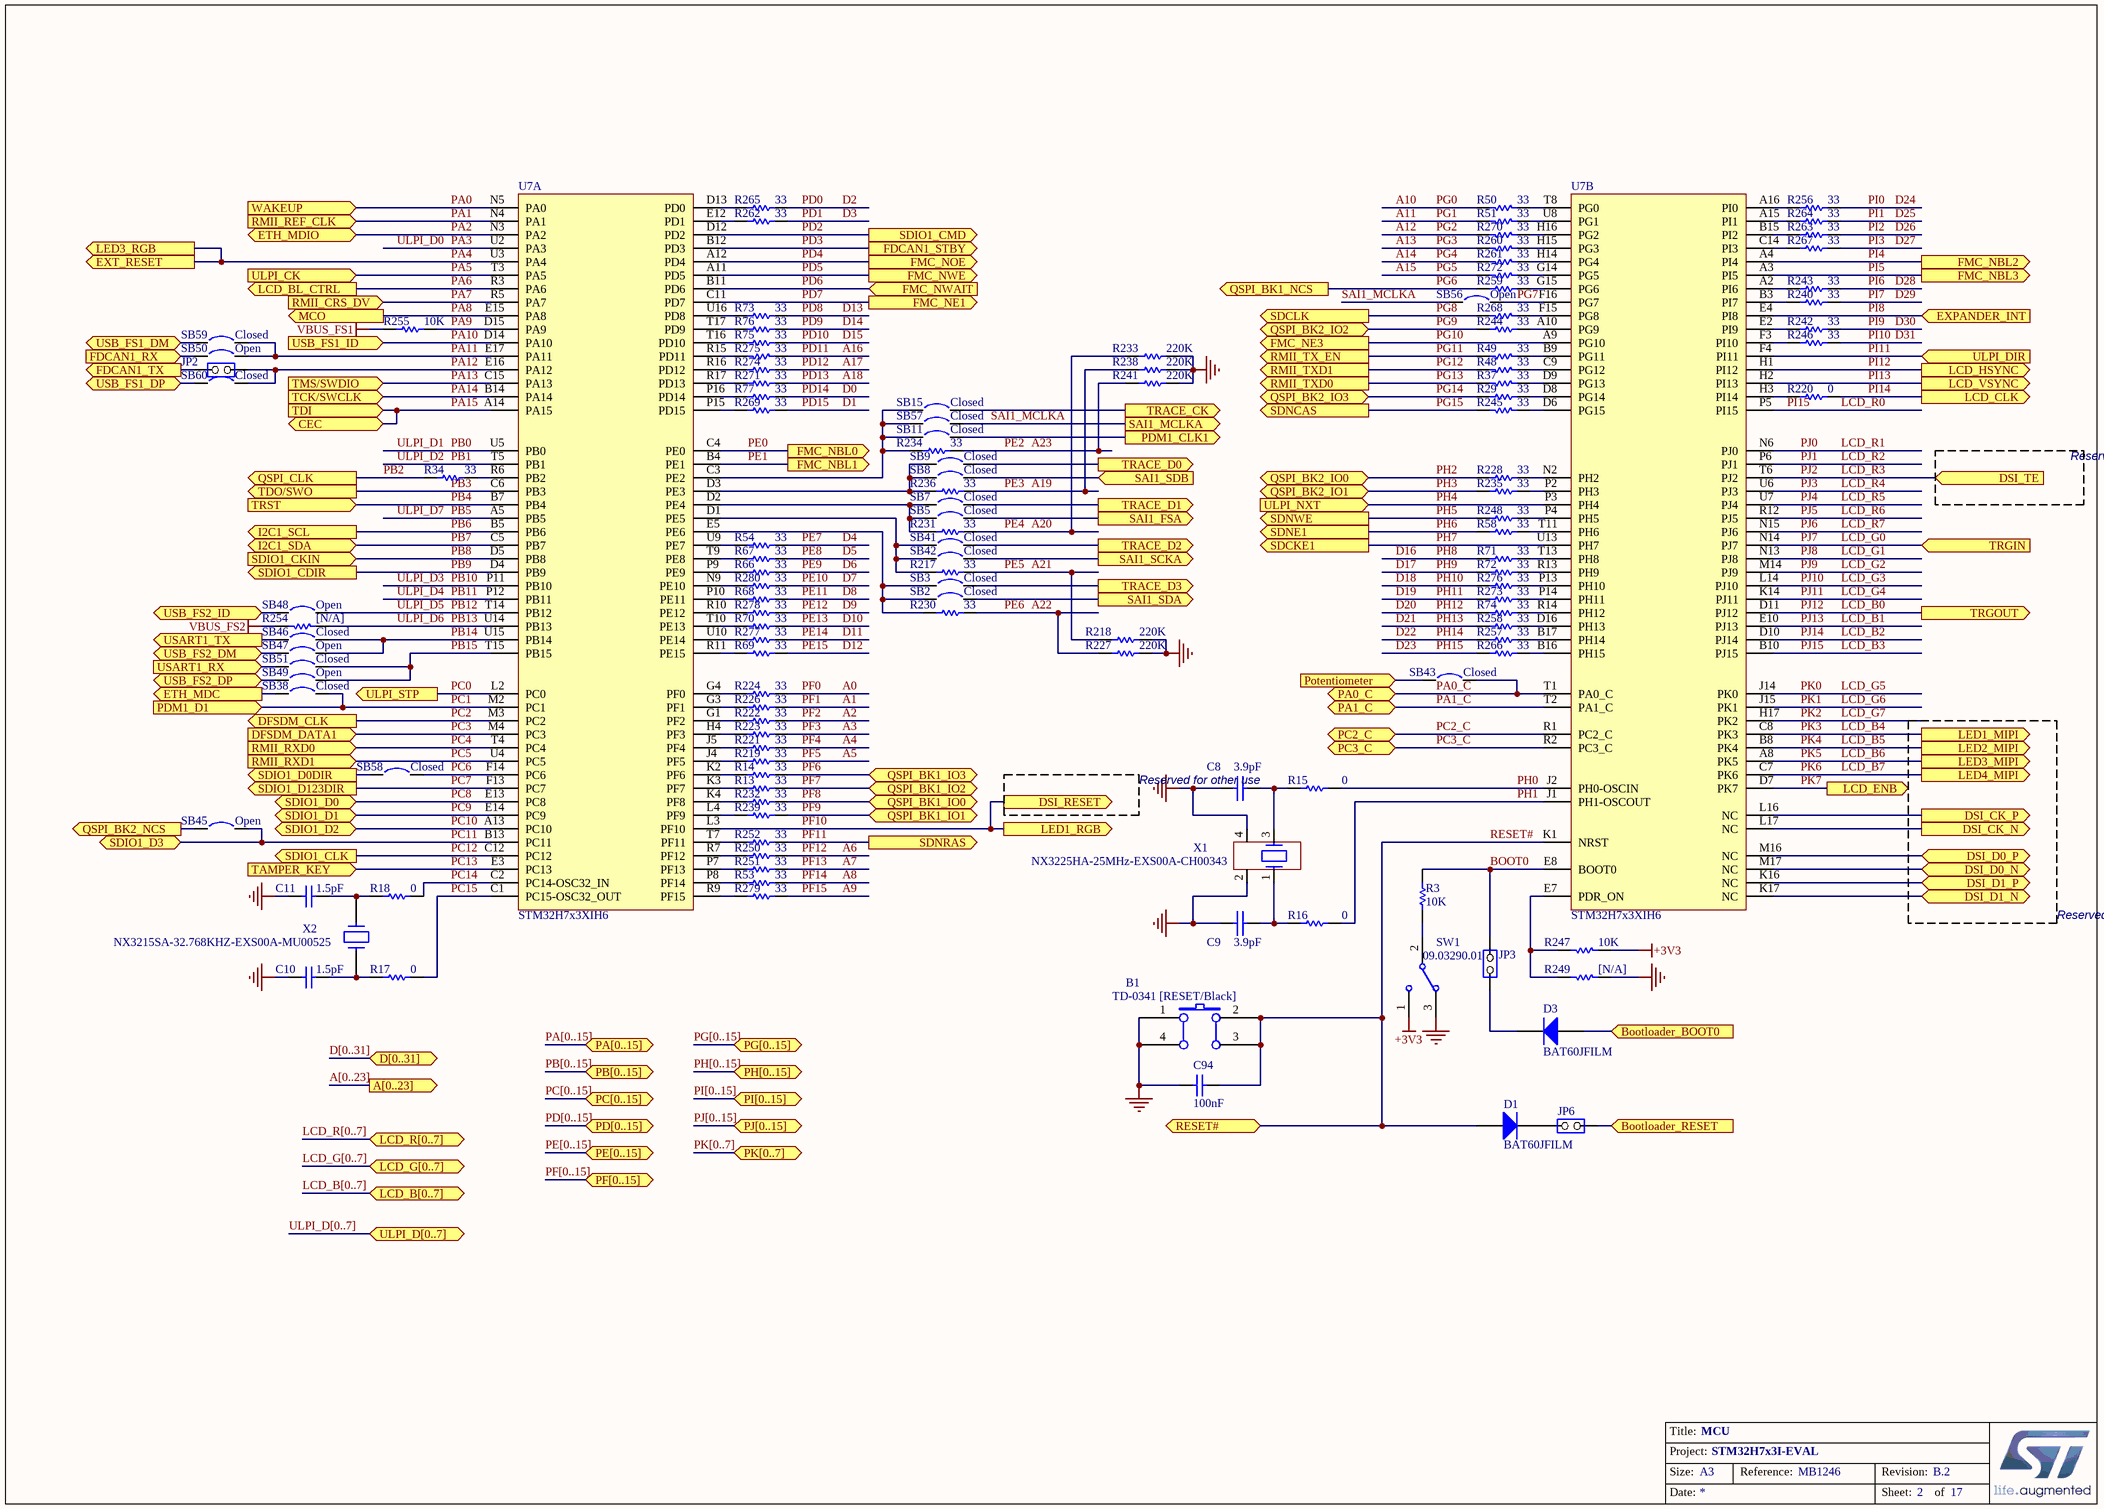
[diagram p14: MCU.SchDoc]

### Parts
B1  TD-0341 [RESET/Black]  [PB10]
C8  3.9pF  [0603C]
C9  3.9pF  [0603C]
C10  1.5pF  [0603C]
C11  1.5pF  [0603C]
C94  100nF  [0603C]
D1  BAT60JFILM  [SOD-323]
D3  BAT60JFILM  [SOD-323]
JP2  (no value)  [SIP2]
JP3  (no value)  [SIP2]
JP6  (no value)  [SIP2]
R3  10K  [0603R]
R13  33  [0402R]
R14  33  [0402R]
R15  0  [0603R]
R16  0  [0603R]
R17  0  [0402R]
R18  0  [0402R]
R29  33  [0402R]
R34  33  [0402R]
R37  33  [0603R]
R48  33  [0603R]
R49  33  [0603R]
R50  33  [0402R]
R51  33  [0402R]
R53  33  [0402R]
R54  33  [0402R]
R58  33  [0402R]
R66  33  [0402R]
R67  33  [0402R]
R68  33  [0402R]
R69  33  [0402R]
R70  33  [0402R]
R71  33  [0402R]
R72  33  [0402R]
R73  33  [0402R]
R74  33  [0402R]
R75  33  [0402R]
R76  33  [0402R]
R77  33  [0402R]
R217  33  [0402R]
R218  220K  [0603R]
R219  33  [0402R]
R220  0  [0603R]
R221  33  [0402R]
R222  33  [0402R]
R223  33  [0402R]
R224  33  [0402R]
R226  33  [0402R]
R227  220K  [0603R]
R228  33  [0402R]
R230  33  [0402R]
R231  33  [0402R]
R232  33  [0402R]
R233  220K  [0603R]
R234  33  [0402R]
R235  33  [0402R]
R236  33  [0402R]
R238  220K  [0603R]
R239  33  [0402R]
R240  33  [0402R]
R241  220K  [0603R]
R242  33  [0402R]
R243  33  [0402R]
R244  33  [0402R]
R245  33  [0402R]
R246  33  [0402R]
R247  10K  [0603R]
R248  33  [0402R]
R249  [N/A]  [0603R]
R250  33  [0402R]
R251  33  [0402R]
R252  33  [0402R]
R254  [N/A]  [0603R]
R255  10K  [0603R]
R256  33  [0402R]
R257  33  [0402R]
R258  33  [0402R]
R259  33  [0402R]
R260  33  [0402R]
R261  33  [0402R]
R262  33  [0402R]
R263  33  [0402R]
R264  33  [0402R]
R265  33  [0402R]
R266  33  [0402R]
R267  33  [0402R]
R268  33  [0402R]
R269  33  [0402R]
R270  33  [0402R]
R271  33  [0402R]
R272  33  [0402R]
R273  33  [0402R]
R274  33  [0402R]
R275  33  [0402R]
R276  33  [0402R]
R277  33  [0402R]
R278  33  [0402R]
R279  33  [0402R]
R280  33  [0402R]
SB2  Closed  [SB_0603]
SB3  Closed  [SB_0603]
SB5  Closed  [SB_0603]
SB7  Closed  [SB_0603]
SB8  Closed  [SB_0603]
SB9  Closed  [SB_0603]
SB11  Closed  [SB_0603]
SB15  Closed  [SB_0603]
SB38  Closed  [SB_0603]
SB41  Closed  [SB_0603]
SB42  Closed  [SB_0603]
SB43  Closed  [SB_0603]
SB45  Open  [SB_0603]
SB46  Closed  [SB_0603]
SB47  Open  [SB_0603]
SB48  Open  [SB_0603]
SB49  Open  [SB_0603]
SB50  Open  [SB_0603]
SB51  Closed  [SB_0603]
SB56  Open  [SB_0603]
SB57  Closed  [SB_0603]
SB58  Closed  [SB_0603]
SB59  Closed  [SB_0603]
SB60  Closed  [SB_0603]
SW1  09.03290.01  [SW1_3TH_2R54_10X2R5]
U7  STM32H7x3XIH6  [BGA265_0R8_14X14_SKT]  (parts A,B of 3)
X1  NX3225HA-25MHz-EXS00A-CH00343  [XTAL_4SM_3R2X2R5]
X2  NX3215SA-32.768KHZ-EXS00A-MU00525  [XTAL_2SM_3R2X1R5]

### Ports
A[0..23] (out), Bootloader_BOOT0 (in), Bootloader_RESET (in), CEC (bidir), D[0..31] (bidir), DFSDM_CLK (out), DFSDM_DATA1 (in), DSI_CK_N (out), DSI_CK_P (out), DSI_D0_N (bidir), DSI_D0_P (bidir), DSI_D1_N (bidir), DSI_D1_P (bidir), DSI_RESET (out), DSI_TE (in), ETH_MDC (out), ETH_MDIO (bidir), EXPANDER_INT (in), EXT_RESET (out), FDCAN1_RX (in), FDCAN1_STBY (out), FDCAN1_TX (out), FMC_NBL0 (out), FMC_NBL1 (out), FMC_NBL2 (out), FMC_NBL3 (out), FMC_NE1 (out), FMC_NE3 (out), FMC_NOE (out), FMC_NWAIT (in), FMC_NWE (out), I2C1_SCL (out), I2C1_SDA (bidir), LCD_B[0..7] (bidir), LCD_BL_CTRL (out), LCD_CLK (out), LCD_ENB (out), LCD_G[0..7] (bidir), LCD_HSYNC (out), LCD_R[0..7] (bidir), LCD_VSYNC (out), LED1_MIPI (out), LED1_RGB (out), LED2_MIPI (out), LED3_MIPI (out), LED3_RGB (out), LED4_MIPI (out), MCO (out), PA0_C (bidir), PA1_C (bidir), PA[0..15] (bidir), PB[0..15] (bidir), PC2_C (bidir), PC3_C (bidir), PC[0..15] (bidir), PD[0..15] (bidir), PDM1_CLK1 (out), PDM1_D1 (in), PE[0..15] (bidir), PF[0..15] (bidir), PG[0..15] (bidir), PH[0..15] (bidir), PI[0..15] (bidir), PJ[0..15] (bidir), PK[0..7] (bidir), Potentiometer (in), QSPI_BK1_IO0 (bidir), QSPI_BK1_IO1 (bidir), QSPI_BK1_IO2 (bidir), QSPI_BK1_IO3 (bidir), QSPI_BK1_NCS (out), QSPI_BK2_IO0 (bidir), QSPI_BK2_IO1 (bidir), QSPI_BK2_IO2 (bidir), QSPI_BK2_IO3 (bidir), QSPI_BK2_NCS (out), QSPI_CLK (out), RESET# (bidir), RMII_CRS_DV (in), RMII_REF_CLK (in), RMII_RXD0 (in), RMII_RXD1 (in), RMII_TX_EN (out), RMII_TXD0 (out), RMII_TXD1 (out), SAI1_FSA (out), SAI1_MCLKA (out), SAI1_SCKA (out), SAI1_SDA (out), SAI1_SDB (in), SDCKE1 (out), SDCLK (out), SDIO1_CDIR (out), SDIO1_CKIN (in), SDIO1_CLK (out), SDIO1_CMD (out), SDIO1_D0 (bidir), SDIO1_D0DIR (out), SDIO1_D1 (bidir), SDIO1_D2 (bidir), SDIO1_D3 (bidir), SDIO1_D123DIR (out), SDNCAS (out), SDNE1 (out), SDNRAS (out), SDNWE (out), TAMPER_KEY (in), TCK/SWCLK (in), TDI (in), TDO/SWO (out), TMS/SWDIO (in), TRACE_CK (out), TRACE_D0 (out), TRACE_D1 (out), TRACE_D2 (out), TRACE_D3 (out), TRGIN (in), TRGOUT (out), TRST (in), ULPI_CK (in), ULPI_D[0..7] (bidir), ULPI_DIR (in), ULPI_NXT (in), ULPI_STP (out), USART1_RX (in), USART1_TX (out), USB_FS1_DM (bidir), USB_FS1_DP (bidir), USB_FS1_ID (in), USB_FS2_DM (bidir), USB_FS2_DP (bidir), USB_FS2_ID (bidir), WAKEUP (in)

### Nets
+3V3: R247.1 SW1.1
GND: B1.1(A0) B1.4(A1) C8.2 C9.2 C10.2 C11.2 C94.1 R218.2 R227.2 R233.2 R238.2 R241.2 R249.1 SW1.3 X1.2 X1.4
VBUS_FS1: R255.1
VBUS_FS2: R254.1
A0: R224.1  [also labelled PF0]
A1: R226.1  [also labelled PF1]
A2: R222.1  [also labelled PF2]
A3: R223.1  [also labelled PF3]
A4: R221.1  [also labelled PF4]
A5: R219.1  [also labelled PF5]
A6: R250.1  [also labelled PF12]
A7: R251.1  [also labelled PF13]
A8: R53.1  [also labelled PF14]
A9: R279.1  [also labelled PF15]
A10: R50.1  [also labelled PG0]
A11: R51.1  [also labelled PG1]
A12: R270.1  [also labelled PG2]
A13: R260.1  [also labelled PG3]
A14: R261.1  [also labelled PG4]
A15: R272.1  [also labelled PG5]
A16: R275.2  [also labelled PD11]
A17: R274.1  [also labelled PD12]
A18: R271.1  [also labelled PD13]
A19: R236.1 R238.1  [also labelled PE3]
A20: R231.1 R233.1  [also labelled PE4]
A21: R217.1 R218.1  [also labelled PE5]
A22: R227.1 R230.1  [also labelled PE6]
A23: R234.1 R241.1  [also labelled PE2]
BOOT0: JP3.2(NO) R3.1 U7.E8(BOOT0)
D0: R77.1  [also labelled PD14]
D1: R269.1  [also labelled PD15]
D2: R265.1  [also labelled PD0]
D3: R262.1  [also labelled PD1]
D4: R54.1  [also labelled PE7]
D5: R67.1  [also labelled PE8]
D6: R66.1  [also labelled PE9]
D7: R280.1  [also labelled PE10]
D8: R68.1  [also labelled PE11]
D9: R278.1  [also labelled PE12]
D10: R70.1  [also labelled PE13]
D11: R277.1  [also labelled PE14]
D12: R69.1  [also labelled PE15]
D13: R73.1  [also labelled PD8]
D14: R76.1  [also labelled PD9]
D15: R75.1  [also labelled PD10]
D16: R71.2  [also labelled PH8]
D17: R72.2  [also labelled PH9]
D18: R276.2  [also labelled PH10]
D19: R273.2  [also labelled PH11]
D20: R74.2  [also labelled PH12]
D21: R258.2  [also labelled PH13]
D22: R257.2  [also labelled PH14]
D23: R266.2  [also labelled PH15]
D24: R256.1  [also labelled PI0]
D25: R264.1  [also labelled PI1]
D26: R263.1  [also labelled PI2]
D27: R267.1  [also labelled PI3]
D28: R243.1  [also labelled PI6]
D29: R240.1  [also labelled PI7]
D30: R242.1  [also labelled PI9]
D31: R246.1  [also labelled PI10]
LCD_B0: U7.D11(PJ12) ; port TRGOUT  [also labelled PJ12]
LCD_B1: U7.E10(PJ13)  [also labelled PJ13]
LCD_B2: U7.D10(PJ14)  [also labelled PJ14]
LCD_B3: U7.B10(PJ15)  [also labelled PJ15]
LCD_B4: U7.C8(PK3) ; port LED1_MIPI  [also labelled PK3]
LCD_B5: U7.B8(PK4) ; port LED2_MIPI  [also labelled PK4]
LCD_B6: U7.A8(PK5) ; port LED3_MIPI  [also labelled PK5]
LCD_B7: U7.C7(PK6) ; port LED4_MIPI  [also labelled PK6]
LCD_G0: U7.N14(PJ7) ; port TRGIN  [also labelled PJ7]
LCD_G1: U7.N13(PJ8)  [also labelled PJ8]
LCD_G2: U7.M14(PJ9)  [also labelled PJ9]
LCD_G3: U7.L14(PJ10)  [also labelled PJ10]
LCD_G4: U7.K14(PJ11)  [also labelled PJ11]
LCD_G5: U7.J14(PK0)  [also labelled PK0]
LCD_G6: U7.J15(PK1)  [also labelled PK1]
LCD_G7: U7.H17(PK2)  [also labelled PK2]
LCD_R0: U7.P5(PI15)  [also labelled PI15]
LCD_R1: U7.N6(PJ0)  [also labelled PJ0]
LCD_R2: U7.P6(PJ1)  [also labelled PJ1]
LCD_R3: U7.T6(PJ2) ; port DSI_TE  [also labelled PJ2]
LCD_R4: U7.U6(PJ3)  [also labelled PJ3]
LCD_R5: U7.U7(PJ4)  [also labelled PJ4]
LCD_R6: U7.R12(PJ5)  [also labelled PJ5]
LCD_R7: U7.N15(PJ6)  [also labelled PJ6]
NCS2: SB45.1 ; port QSPI_BK2_NCS
PA0: U7.N5(PA0) ; port WAKEUP
PA0_C: SB43.1 U7.T1(PA0_C) ; port PA0_C
PA1: U7.N4(PA1) ; port RMII_REF_CLK
PA1_C: U7.T2(PA1_C) ; port PA1_C
PA2: U7.N3(PA2) ; port ETH_MDIO
PA3: U7.U2(PA3)  [also labelled ULPI_D0]
PA4: U7.U3(PA4) ; port EXT_RESET, port LED3_RGB
PA5: U7.T3(PA5) ; port ULPI_CK
PA6: U7.R3(PA6) ; port LCD_BL_CTRL  [project net LCD_BL_CTRL]
PA7: U7.R5(PA7) ; port RMII_CRS_DV
PA8: U7.E15(PA8) ; port MCO
PA9: R255.2 U7.D15(PA9)
PA10: U7.D14(PA10) ; port USB_FS1_ID
PA11: SB50.2 SB59.2 U7.E17(PA11)
PA12: JP2.1(COMMON) SB60.2 U7.E16(PA12)
PA13: U7.C15(PA13) ; port TMS/SWDIO
PA14: U7.B14(PA14) ; port TCK/SWCLK
PA15: U7.A14(PA15) ; port TDI, port CEC
PB0: U7.U5(PB0)  [also labelled ULPI_D1]
PB1: U7.T5(PB1)  [also labelled ULPI_D2]
PB2: R34.2 ; port QSPI_CLK
PB3: U7.C6(PB3) ; port TDO/SWO
PB4: U7.B7(PB4) ; port TRST
PB5: U7.A5(PB5)  [also labelled ULPI_D7]
PB6: U7.B5(PB6) ; port I2C1_SCL  [project net I2C1_SCL]
PB7: U7.C5(PB7) ; port I2C1_SDA  [project net I2C1_SDA]
PB8: U7.D5(PB8) ; port SDIO1_CKIN
PB9: U7.D4(PB9) ; port SDIO1_CDIR
PB10: U7.P11(PB10)  [also labelled ULPI_D3]
PB11: U7.P12(PB11)  [also labelled ULPI_D4]
PB12: SB48.2 U7.T14(PB12)  [also labelled ULPI_D5]
PB13: R254.2 U7.U14(PB13)  [also labelled ULPI_D6]
PB14: SB46.2 SB47.2 U7.U15(PB14)
PB15: SB49.2 SB51.2 U7.T15(PB15)
PC0: U7.L2(PC0) ; port ULPI_STP
PC1: SB38.2 U7.M2(PC1) ; port PDM1_D1
PC2: U7.M3(PC2) ; port DFSDM_CLK
PC2_C: U7.R1(PC2_C) ; port PC2_C
PC3: U7.M4(PC3) ; port DFSDM_DATA1
PC3_C: U7.R2(PC3_C) ; port PC3_C
PC4: U7.T4(PC4) ; port RMII_RXD0
PC5: U7.U4(PC5) ; port RMII_RXD1
PC6: SB58.1 U7.F14(PC6)
PC7: U7.F13(PC7) ; port SDIO1_D123DIR
PC8: U7.E13(PC8) ; port SDIO1_D0
PC9: U7.E14(PC9) ; port SDIO1_D1
PC10: U7.A13(PC10) ; port SDIO1_D2
PC11: SB45.2 U7.B13(PC11) ; port SDIO1_D3
PC12: U7.C12(PC12) ; port SDIO1_CLK
PC13: U7.E3(PC13) ; port TAMPER_KEY
PC14: R18.1 U7.C2(PC14-OSC32_IN)
PC15: R17.1 U7.C1(PC15-OSC32_OUT)
PD2: U7.D12(PD2) ; port SDIO1_CMD
PD3: U7.B12(PD3) ; port FDCAN1_STBY
PD4: U7.A12(PD4) ; port FMC_NOE
PD5: U7.A11(PD5) ; port FMC_NWE
PD6: U7.B11(PD6) ; port FMC_NWAIT
PD7: U7.C11(PD7) ; port FMC_NE1
PE0: U7.C4(PE0) ; port FMC_NBL0
PE1: U7.B4(PE1) ; port FMC_NBL1
PF6: R14.1 ; port QSPI_BK1_IO3
PF7: R13.1 ; port QSPI_BK1_IO2
PF8: R232.1 ; port QSPI_BK1_IO0
PF9: R239.1 ; port QSPI_BK1_IO1
PF10: U7.L3(PF10) ; port DSI_RESET, port LED1_RGB
PF11: R252.1 ; port SDNRAS
PG6: R259.2 ; port QSPI_BK1_NCS
PG7: SB56.2 U7.F16(PG7)
PG8: R268.1 ; port SDCLK
PG9: R244.2 ; port QSPI_BK2_IO2  [project net BK2_IO2]
PG10: U7.A9(PG10) ; port FMC_NE3
PG11: R49.1 ; port RMII_TX_EN
PG12: R48.1 ; port RMII_TXD1
PG13: R37.1 ; port RMII_TXD0
PG14: R29.2 ; port QSPI_BK2_IO3  [project net BK2_IO3]
PG15: R245.1 ; port SDNCAS
PH0: R15.2 U7.J2(PH0-OSCIN)
PH1: R16.2 U7.J1(PH1-OSCOUT)
PH2: R228.2 ; port QSPI_BK2_IO0  [project net BK2_IO0]
PH3: R235.2 ; port QSPI_BK2_IO1  [project net BK2_IO1]
PH4: U7.P3(PH4) ; port ULPI_NXT
PH5: R248.2 ; port SDNWE
PH6: R58.2 ; port SDNE1
PH7: U7.U13(PH7) ; port SDCKE1
PI4: U7.A4(PI4) ; port FMC_NBL2
PI5: U7.A3(PI5) ; port FMC_NBL3
PI8: U7.E4(PI8) ; port EXPANDER_INT
PI11: U7.F4(PI11) ; port ULPI_DIR
PI12: U7.H1(PI12) ; port LCD_HSYNC
PI13: U7.H2(PI13) ; port LCD_VSYNC
PI14: R220.1 ; port LCD_CLK
PK7: U7.D7(PK7) ; port LCD_ENB
RESET#: B1.2(B0) B1.3(B1) C94.2 D1.1(A) U7.K1(NRST) ; port RESET#
SAI1_MCLKA: SB56.1 SB57.1 ; port SAI1_MCLKA
NetC8_1: C8.1 R15.1 X1.3
NetC9_1: C9.1 R16.1 X1.1
NetC10_1: C10.1 R17.2 X2.1
NetC11_1: C11.1 R18.2 X2.2
NetCN8_12: SB15.1 ; port TRACE_CK
NetCN8_14: SB9.1 ; port TRACE_D0
NetCN8_16: SB7.1 ; port TRACE_D1
NetCN8_18: SB41.1 ; port TRACE_D2
NetCN8_20: SB3.1 ; port TRACE_D3
NetCN15_3: U7.L16(NC) ; port DSI_CK_P
NetCN15_5: U7.L17(NC) ; port DSI_CK_N
NetCN15_9: U7.M16(NC) ; port DSI_D0_P
NetCN15_11: U7.M17(NC) ; port DSI_D0_N
NetCN15_15: U7.K16(NC) ; port DSI_D1_P
NetCN15_17: U7.K17(NC) ; port DSI_D1_N
NetCN15_35: SB42.1 ; port SAI1_SCKA
NetCN15_37: SB5.1 ; port SAI1_FSA
NetCN15_39: SB2.1 ; port SAI1_SDA
NetCN16_2: SB47.1 ; port USB_FS2_DM
NetCN16_3: SB49.1 ; port USB_FS2_DP
NetCN16_4: SB48.1 ; port USB_FS2_ID
NetCN18_2: SB59.1 ; port USB_FS1_DM
NetCN18_3: SB60.1 ; port USB_FS1_DP
NetD1_2: D1.2(K) JP6.1(COMMON)
NetD3_1: D3.1(A) ; port Bootloader_BOOT0
NetD3_2: D3.2(K) JP3.1(COMMON)
NetJP2_2: JP2.2(NO) ; port FDCAN1_TX
NetJP6_2: JP6.2(NO) ; port Bootloader_RESET
NetJP7_2: SB46.1 ; port USART1_TX
NetJP8_2: SB51.1 ; port USART1_RX
NetM1_23: SB58.2 ; port SDIO1_D0DIR
NetR3_2: R3.2 SW1.2
NetR12_2: SB43.2 ; port Potentiometer
NetR13_2: R13.2 U7.K3(PF7)
NetR14_2: R14.2 U7.K2(PF6)
NetR29_1: R29.1 U7.D8(PG14)
NetR34_1: R34.1 U7.R6(PB2)
NetR37_2: R37.2 U7.D9(PG13)
NetR48_2: R48.2 U7.C9(PG12)
NetR49_2: R49.2 U7.B9(PG11)
NetR50_2: R50.2 U7.T8(PG0)
NetR51_2: R51.2 U7.U8(PG1)
NetR53_2: R53.2 U7.P8(PF14)
NetR54_2: R54.2 U7.U9(PE7)
NetR58_1: R58.1 U7.T11(PH6)
NetR66_2: R66.2 U7.P9(PE9)
NetR67_2: R67.2 U7.T9(PE8)
NetR68_2: R68.2 U7.P10(PE11)
NetR69_2: R69.2 U7.R11(PE15)
NetR70_2: R70.2 U7.T10(PE13)
NetR71_1: R71.1 U7.T13(PH8)
NetR72_1: R72.1 U7.R13(PH9)
NetR73_2: R73.2 U7.U16(PD8)
NetR74_1: R74.1 U7.R14(PH12)
NetR75_2: R75.2 U7.T16(PD10)
NetR76_2: R76.2 U7.T17(PD9)
NetR77_2: R77.2 U7.P16(PD14)
NetR217_2: R217.2 SB41.2 SB42.2 U7.D1(PE5)
NetR219_2: R219.2 U7.J4(PF5)
NetR220_2: R220.2 U7.H3(PI14)
NetR221_2: R221.2 U7.J5(PF4)
NetR222_2: R222.2 U7.G1(PF2)
NetR223_2: R223.2 U7.H4(PF3)
NetR224_2: R224.2 U7.G4(PF0)
NetR226_2: R226.2 U7.G3(PF1)
NetR228_1: R228.1 U7.N2(PH2)
NetR230_2: R230.2 SB2.2 SB3.2 U7.E5(PE6)
NetR231_2: R231.2 SB5.2 SB7.2 U7.D2(PE4)
NetR232_2: R232.2 U7.K4(PF8)
NetR234_2: R234.2 SB11.2 SB15.2 SB57.2 U7.C3(PE2)
NetR235_1: R235.1 U7.P2(PH3)
NetR236_2: R236.2 SB8.2 SB9.2 U7.D3(PE3)
NetR239_2: R239.2 U7.L4(PF9)
NetR240_2: R240.2 U7.B3(PI7)
NetR242_2: R242.2 U7.E2(PI9)
NetR243_2: R243.2 U7.A2(PI6)
NetR244_1: R244.1 U7.A10(PG9)
NetR245_2: R245.2 U7.D6(PG15)
NetR246_2: R246.2 U7.F3(PI10)
NetR247_2: R247.2 R249.2 U7.E7(PDR_ON)
NetR248_1: R248.1 U7.P4(PH5)
NetR250_2: R250.2 U7.R7(PF12)
NetR251_2: R251.2 U7.P7(PF13)
NetR252_2: R252.2 U7.T7(PF11)
NetR256_2: R256.2 U7.A16(PI0)
NetR257_1: R257.1 U7.B17(PH14)
NetR258_1: R258.1 U7.D16(PH13)
NetR259_1: R259.1 U7.G15(PG6)
NetR260_2: R260.2 U7.H15(PG3)
NetR261_2: R261.2 U7.H14(PG4)
NetR262_2: R262.2 U7.E12(PD1)
NetR263_2: R263.2 U7.B15(PI2)
NetR264_2: R264.2 U7.A15(PI1)
NetR265_2: R265.2 U7.D13(PD0)
NetR266_1: R266.1 U7.B16(PH15)
NetR267_2: R267.2 U7.C14(PI3)
NetR268_2: R268.2 U7.F15(PG8)
NetR269_2: R269.2 U7.P15(PD15)
NetR270_2: R270.2 U7.H16(PG2)
NetR271_2: R271.2 U7.R17(PD13)
NetR272_2: R272.2 U7.G14(PG5)
NetR273_1: R273.1 U7.P14(PH11)
NetR274_2: R274.2 U7.R16(PD12)
NetR275_1: R275.1 U7.R15(PD11)
NetR276_1: R276.1 U7.P13(PH10)
NetR277_2: R277.2 U7.U10(PE14)
NetR278_2: R278.2 U7.R10(PE12)
NetR279_2: R279.2 U7.R9(PF15)
NetR280_2: R280.2 U7.N9(PE10)
NetSB8_1: SB8.1 ; port SAI1_SDB
NetSB11_1: SB11.1 ; port PDM1_CLK1
NetSB38_1: SB38.1 ; port ETH_MDC
NetSB50_1: SB50.1 ; port FDCAN1_RX

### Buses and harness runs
bus A[0..23] = port A[0..23]
bus D[0..31] = port D[0..31]
bus LCD_B[0..7] = port LCD_B[0..7]
bus LCD_G[0..7] = port LCD_G[0..7]
bus LCD_R[0..7] = port LCD_R[0..7]
bus PA[0..15] = port PA[0..15]
bus PB[0..15] = port PB[0..15]
bus PC[0..15] = port PC[0..15]
bus PD[0..15] = port PD[0..15]
bus PE[0..15] = port PE[0..15]
bus PF[0..15] = port PF[0..15]
bus PG[0..15] = port PG[0..15]
bus PH[0..15] = port PH[0..15]
bus PI[0..15] = port PI[0..15]
bus PJ[0..15] = port PJ[0..15]
bus PK[0..7] = port PK[0..7]
bus ULPI_D[0..7] = port ULPI_D[0..7]

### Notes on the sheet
- Reserved for other use

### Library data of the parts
B1 = SW PUSHBUTTON: SE PUSHBUTTON
C8 C9 = CAP: Capacitor
C10 C11 = Capacitor_ST: as C78 on sheet ST_LINK_V2-1
C94 = CAP: Capacitor; Value: 100pF
D1 D3 = Diode: Default Diode; Code - JEDEC: DO-214-AB
JP2 JP3 JP6 = JP2
R3 R218 R227 R233 R238 R241 = res1: Resistor; Value: 1K
R13-R18 R29 R34 R37 R48-R51 R53 R54 R58 R66-R77 R217 R219-R224 R226 R228 R230-R232 R234-R236 R239 R240 R242-R252 R254-R280 = Res1: Resistor; Value: 1K
SB2 SB3 SB5 SB7-SB9 SB11 SB15 SB38 SB41-SB43 SB46 SB51 SB57-SB60 = Circuit Breaker_close: Circuit Breaker
SB45 SB47-SB50 SB56 = Circuit Breaker
SW1 = SW-SPDT: SPDT Subminiature Toggle Switch, Right Angle Mounting, Vertical Actuation; Revision 1: Jul-2002: Re-released for DXP Platform.; Revision 2: 17-Dec-2003: Schematic revised, PCB Footprint replaced.
U7 = STM32H7x3XIH6_TFBGA265
X2 = CRYSTAL_32K: Crystal

## Sheet USB_OTG.SchDoc: USB_OTG_HS
size A4; DocumentNumber: MB1246; Revision: B.2; SheetNumber: 8; SheetTotal: 17; Project: STM32H7x3I-EVAL
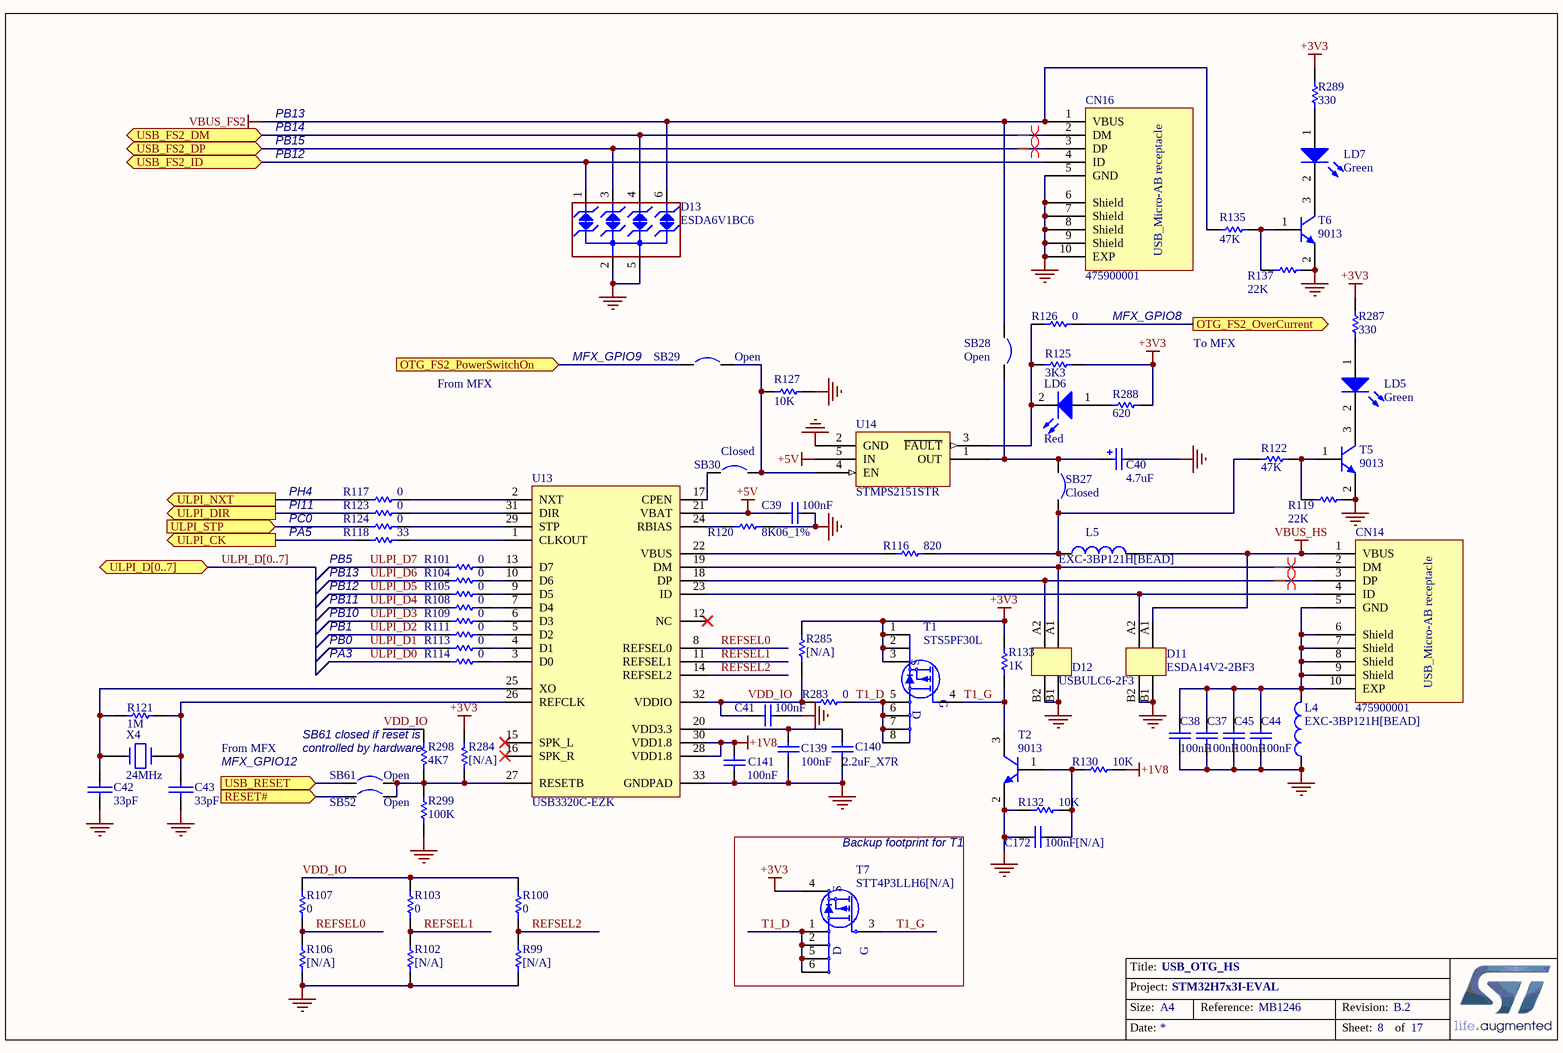
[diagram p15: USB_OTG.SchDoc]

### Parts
C37  100nF  [0603C]
C38  100nF  [0603C]
C39  100nF  [0603C]
C40  4.7uF  [TAN-A]
C41  100nF  [0603C]
C42  33pF  [0603C]
C43  33pF  [0603C]
C44  100nF  [0603C]
C45  100nF  [0603C]
C139  100nF  [0603C]
C140  2.2uF_X7R  [0603C]
C141  100nF  [0603C]
C172  100nF[N/A]  [0603C]
CN14  475900001  [MOLEX_47590001]
CN16  475900001  [MOLEX_47590001]
D11  ESDA14V2-2BF3  [BGA4_0R4_0R8X0R8]
D12  USBULC6-2F3  [BGA4_0R4_1X1]
D13  ESDA6V1BC6  [SOT23-6L]
L4  EXC-3BP121H[BEAD]  [0603L]
L5  EXC-3BP121H[BEAD]  [0603L]
LD5  Green  [0603D]
LD6  Red  [0603D]
LD7  Green  [0603D]
R99  [N/A]  [0603R]
R100  0  [0603R]
R101  0  [0603R]
R102  [N/A]  [0603R]
R103  0  [0603R]
R104  0  [0603R]
R105  0  [0603R]
R106  [N/A]  [0603R]
R107  0  [0603R]
R108  0  [0603R]
R109  0  [0603R]
R111  0  [0603R]
R113  0  [0603R]
R114  0  [0603R]
R116  820  [0603R]
R117  0  [0603R]
R118  33  [0603R]
R119  22K  [0603R]
R120  8K06_1%  [0603R]
R121  1M  [0603R]
R122  47K  [0603R]
R123  0  [0603R]
R124  0  [0603R]
R125  3K3  [0603R]
R126  0  [0603R]
R127  10K  [0603R]
R130  10K  [0603R]
R132  10K  [0603R]
R133  1K  [0603R]
R135  47K  [0603R]
R137  22K  [0603R]
R283  0  [0603R]
R284  [N/A]  [0603R]
R285  [N/A]  [0603R]
R287  330  [0603R]
R288  620  [0603R]
R289  330  [0603R]
R298  4K7  [0603R]
R299  100K  [0603R]
SB27  Closed  [SB_0603]
SB28  Open  [SB_0603]
SB29  Open  [SB_0603]
SB30  Closed  [SB_0603]
SB52  Open  [SB_0603]
SB61  Open  [SB_0603]
T1  STS5PF30L  [SOIC8_1R27_4R9X6]
T2  9013  [SOT-23]
T5  9013  [SOT-23]
T6  9013  [SOT-23]
T7  STT4P3LLH6[N/A]  [SOT23-6L]
U13  USB3320C-EZK  [QFN32_0R5_5X5]
U14  STMPS2151STR  [SOT23-5]
X4  24MHz  [XTAL1]

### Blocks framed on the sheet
Backup footprint for T1: T7

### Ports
OTG_FS2_OverCurrent (out), OTG_FS2_PowerSwitchOn (in), RESET# (in), ULPI_CK (out), ULPI_D[0..7] (bidir), ULPI_DIR (out), ULPI_NXT (out), ULPI_STP (in), USB_FS2_DM (bidir), USB_FS2_DP (bidir), USB_FS2_ID (bidir), USB_RESET (in)

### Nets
+1V8: C141.1 R130.1 U13.28(VDD1.8) U13.30(VDD1.8)
+3V3: R125.1 R133.2 R284.2 R285.1 R287.2 R288.2 R289.2 T1.1(S) T1.2(S) T1.3(S) T7.4(S)
+5V: C39.1 U13.21(VBAT) U14.5(IN)
GND: C37.2 C38.2 C39.2 C40.2 C41.2 C42.2 C43.2 C44.2 C45.2 C139.2 C140.1 C141.2 C172.2 CN16.5(GND) CN16.6(Shield) CN16.7(Shield) CN16.8(Shield) CN16.9(Shield) CN16.10(EXP) D11.B1 D11.B2 D12.B1 D12.B2 D13.2(IO2) D13.5(IO4) L4.1 R99.1 R102.1 R106.1 R119.1 R120.2 R127.1 R132.2 R137.1 R299.1 T2.2(E) T5.2(E) T6.2(E) U13.33(GNDPAD) U14.2(GND)
VBUS_FS2: CN16.1(VBUS) D13.6(NC) R135.1 SB28.1
VBUS_HS: CN14.1(VBUS) D11.A1 L5.2
PA5: R118.2 ; port ULPI_CK
PC0: R124.2 ; port ULPI_STP
PH4: R117.2 ; port ULPI_NXT
PI11: R123.2 ; port ULPI_DIR
REFSEL0: R106.2 R107.1 U13.8(REFSEL0)
REFSEL1: R102.2 R103.1 U13.11(REFSEL1)
REFSEL2: R99.2 R100.1 U13.14(REFSEL2)
RESET#: SB52.1 ; port RESET#
T1_D: R283.1 T1.5(D) T1.6(D) T1.7(D) T1.8(D) T7.1(S) T7.2(S) T7.5(D) T7.6(D)
T1_G: R133.1 T1.4(G) T2.3(C) T7.3(G)
ULPI_D0: R114.2  [project net PA3]
ULPI_D1: R113.2  [project net PB0]
ULPI_D2: R111.2  [project net PB1]
ULPI_D3: R109.2  [project net PB10]
ULPI_D4: R108.2  [project net PB11]
ULPI_D5: R105.2  [project net PB12]
ULPI_D6: R104.2  [project net PB13]
ULPI_D7: R101.2  [project net PB5]
VDD_IO: C41.1 R100.2 R103.2 R107.2 R283.2 R285.2 R298.2 U13.32(VDDIO)
NetC37_1: C37.1 C38.1 C44.1 C45.1 CN14.5(GND) CN14.6(Shield) CN14.7(Shield) CN14.8(Shield) CN14.9(Shield) CN14.10(EXP) L4.2
NetC40_1: C40.1 SB27.1 SB28.2 U14.1(OUT)
NetC42_1: C42.1 R121.1 U13.25(XO) X4.2
NetC43_1: C43.1 R121.2 U13.26(REFCLK) X4.1
NetC139_1: C139.1 C140.2 U13.20(VDD3.3)
NetC172_1: C172.1 R130.2 R132.1 T2.1(B)
NetCN14_2: CN14.2(DM) D12.A1 U13.19(DM)
NetCN14_3: CN14.3(DP) D12.A2 U13.18(DP)
NetCN14_4: CN14.4(ID) D11.A2 U13.23(ID)
NetCN16_2: CN16.2(DM) D13.4(IO3) ; port USB_FS2_DM
NetCN16_3: CN16.3(DP) D13.3(GND) ; port USB_FS2_DP
NetCN16_4: CN16.4(ID) D13.1(IO1) ; port USB_FS2_ID
NetL5_1: L5.1 R116.2 R122.2 SB27.2
NetLD5_1: LD5.1(A) R287.1
NetLD5_2: LD5.2(K) T5.3(C)
NetLD6_1: LD6.1(A) R288.1
NetLD6_2: LD6.2(K) R125.2 R126.2 U14.3(~{FAULT})
NetLD7_1: LD7.1(A) R289.1
NetLD7_2: LD7.2(K) T6.3(C)
NetR101_1: R101.1 U13.13(D7)
NetR104_1: R104.1 U13.10(D6)
NetR105_1: R105.1 U13.9(D5)
NetR108_1: R108.1 U13.7(D4)
NetR109_1: R109.1 U13.6(D3)
NetR111_1: R111.1 U13.5(D2)
NetR113_1: R113.1 U13.4(D1)
NetR114_1: R114.1 U13.3(D0)
NetR116_1: R116.1 U13.22(VBUS)
NetR117_1: R117.1 U13.2(NXT)
NetR118_1: R118.1 U13.1(CLKOUT)
NetR119_2: R119.2 R122.1 T5.1(B)
NetR120_1: R120.1 U13.24(RBIAS)
NetR123_1: R123.1 U13.31(DIR)
NetR124_1: R124.1 U13.29(STP)
NetR126_1: R126.1 ; port OTG_FS2_OverCurrent
NetR127_2: R127.2 SB29.2 SB30.2 U14.4(EN)
NetR135_2: R135.2 R137.2 T6.1(B)
NetR284_1: R284.1 R298.1 R299.2 SB52.2 SB61.2 U13.27(RESETB)
NetSB29_1: SB29.1 ; port OTG_FS2_PowerSwitchOn
NetSB30_1: SB30.1 U13.17(CPEN)
NetSB61_1: SB61.1 ; port USB_RESET

Not connected (* = marked no-connect by the designer): U13 12(NC)* 15(SPK_L)* 16(SPK_R)*

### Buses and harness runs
bus ULPI_D[0..7] = port ULPI_D[0..7]

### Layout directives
differential pair: NetCN14_2, NetCN14_3, NetCN16_2, NetCN16_3

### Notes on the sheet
- PB13
- PB12
- PB14
- PB15
- MFX_GPIO8
- From MFX
- MFX_GPIO9
- To MFX
- PH4
- PI11
- PC0
- PA5
- PB5
- PA3
- PB0
- PB1
- PB10
- PB11
- MFX_GPIO12
- (near R298) SB61 closed if reset is
- (near R298) controlled by hardware

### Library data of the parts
C37-C39 C41 C44 C45 C139-C141 = Cap: Capacitor; Value: 10nF
C40 = Cap Pol1: as C53 on sheet USB_OTG_FS
C42 C43 = CAP: Capacitor
C172 = Cap_100nF_X7R_10%_0402: Capacitor,100nF,16V,X7R,10%,0402,YAGEO; Manuf_Part_1: CC0402KRX7R7BB104
D13 = ESDA6V1BC6: as D14 on sheet USB_OTG_FS
L4 L5 = Inductor: Value: 100uH
LD5-LD7 = LED2: as LD11 on sheet ST_LINK_V2-1
R99-R109 R111 R113 R114 R117 R118 R121 R123 R124 R126 R283-R285 R288 R298 = Res1: Resistor; Value: 1K
R116 R119 R122 R125 R127 R130 R132 R135 R137 R287 R289 = res1: Resistor; Value: 1K
R120 = Res_8K06_1%_0402: Resistor,8K06,0402,1%,YAGEO; Manuf_Part_1: RC0402FR-078K06L
R133 = res1: Resistor
R299 = Resistor_ST: as R138 on sheet ST_LINK_V2-1
SB27 SB30 = Circuit Breaker_close: Circuit Breaker
SB28 SB29 SB52 SB61 = Circuit Breaker
T1 = STS7PF30L
T2 T5 T6 = NPN: as T4 on sheet ST_LINK_V2-1
T7 = STT7P2UH7: STripFET VII DeepGATE Power MOSFET, P-CHANNEL 20 V, 0.0146, 7 A - SOT23-6L; Manuf_1: STM; Provided: ST; Ref St: xxxxxxxx; ECCN_US/EU: EAR99/NEC; Comments: exclusive with T4
U13 = USB3320C-EZK: USB3320C,  Hi-Speed USB Host, Device or OTG PHY with ULPI Low Pin Interface; Manuf_1: MICROCHIP; Manuf_Part_1: USB3320C-EZK-TR
U14 = STMPS2141STR
X4 = CRYSTAL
